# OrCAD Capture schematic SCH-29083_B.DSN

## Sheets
1 02 NOTES: title: TWR-CM3120-EVM; rev: B; company: NXP SEMICONDUCTORS; note: SCH-29083 PDF: SPF-29083; note: 6501 William Cannon Drive West; note: Austin, TX 78735-8598
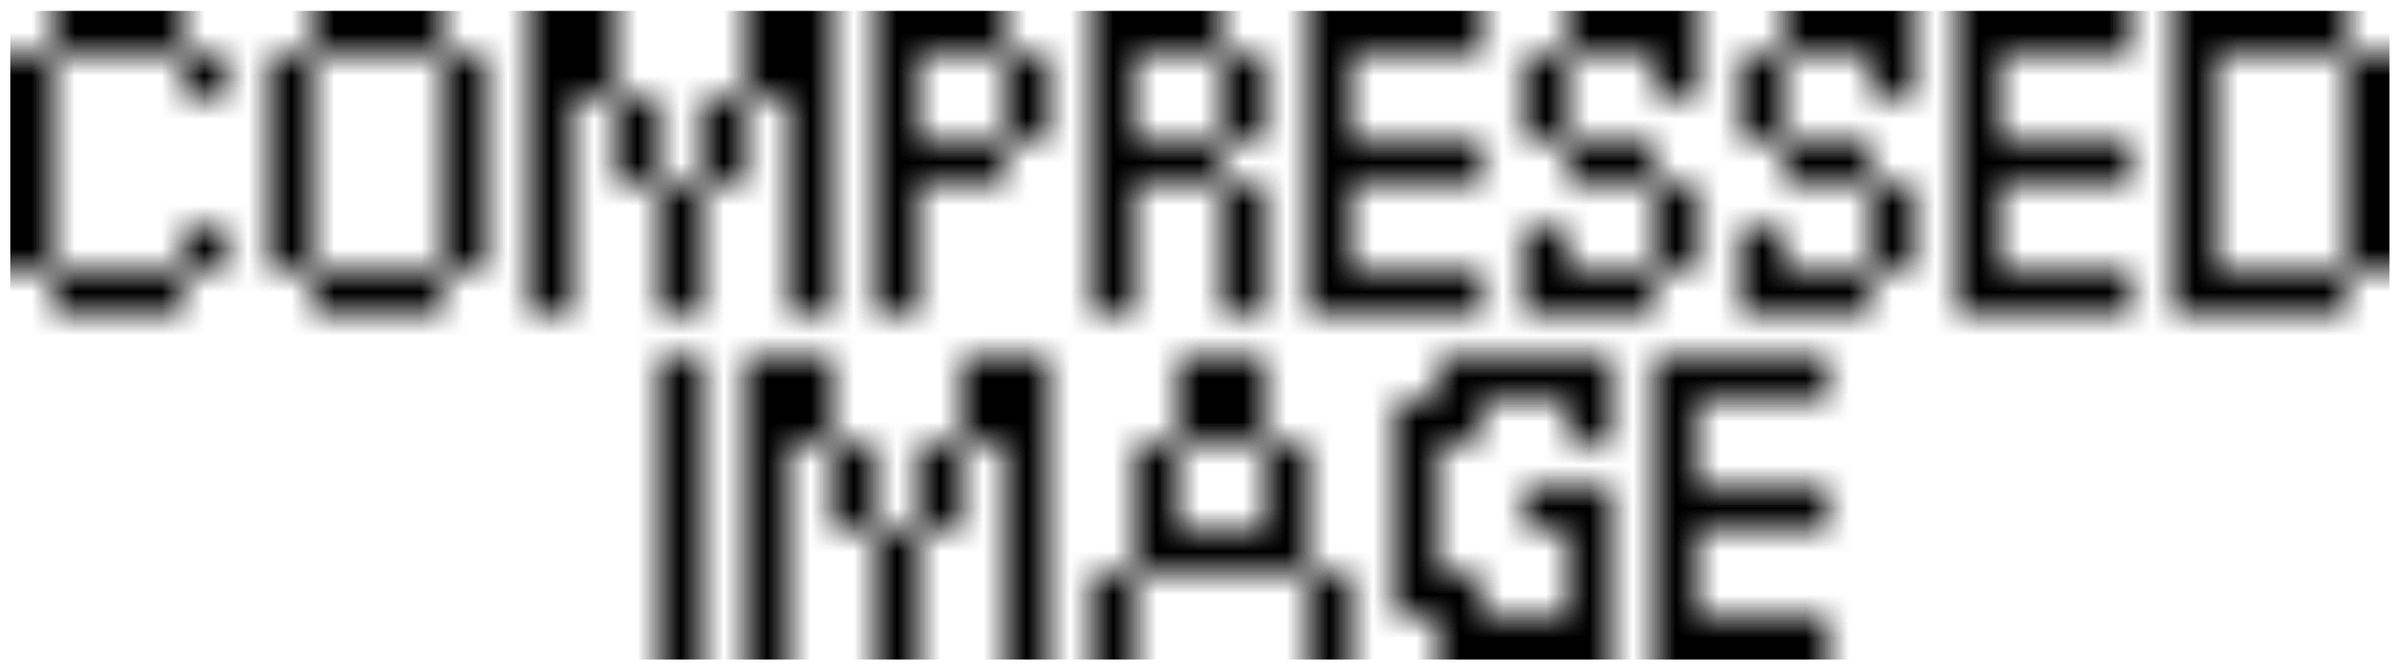
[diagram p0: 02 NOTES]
2 01 TITLE, TOC & REV
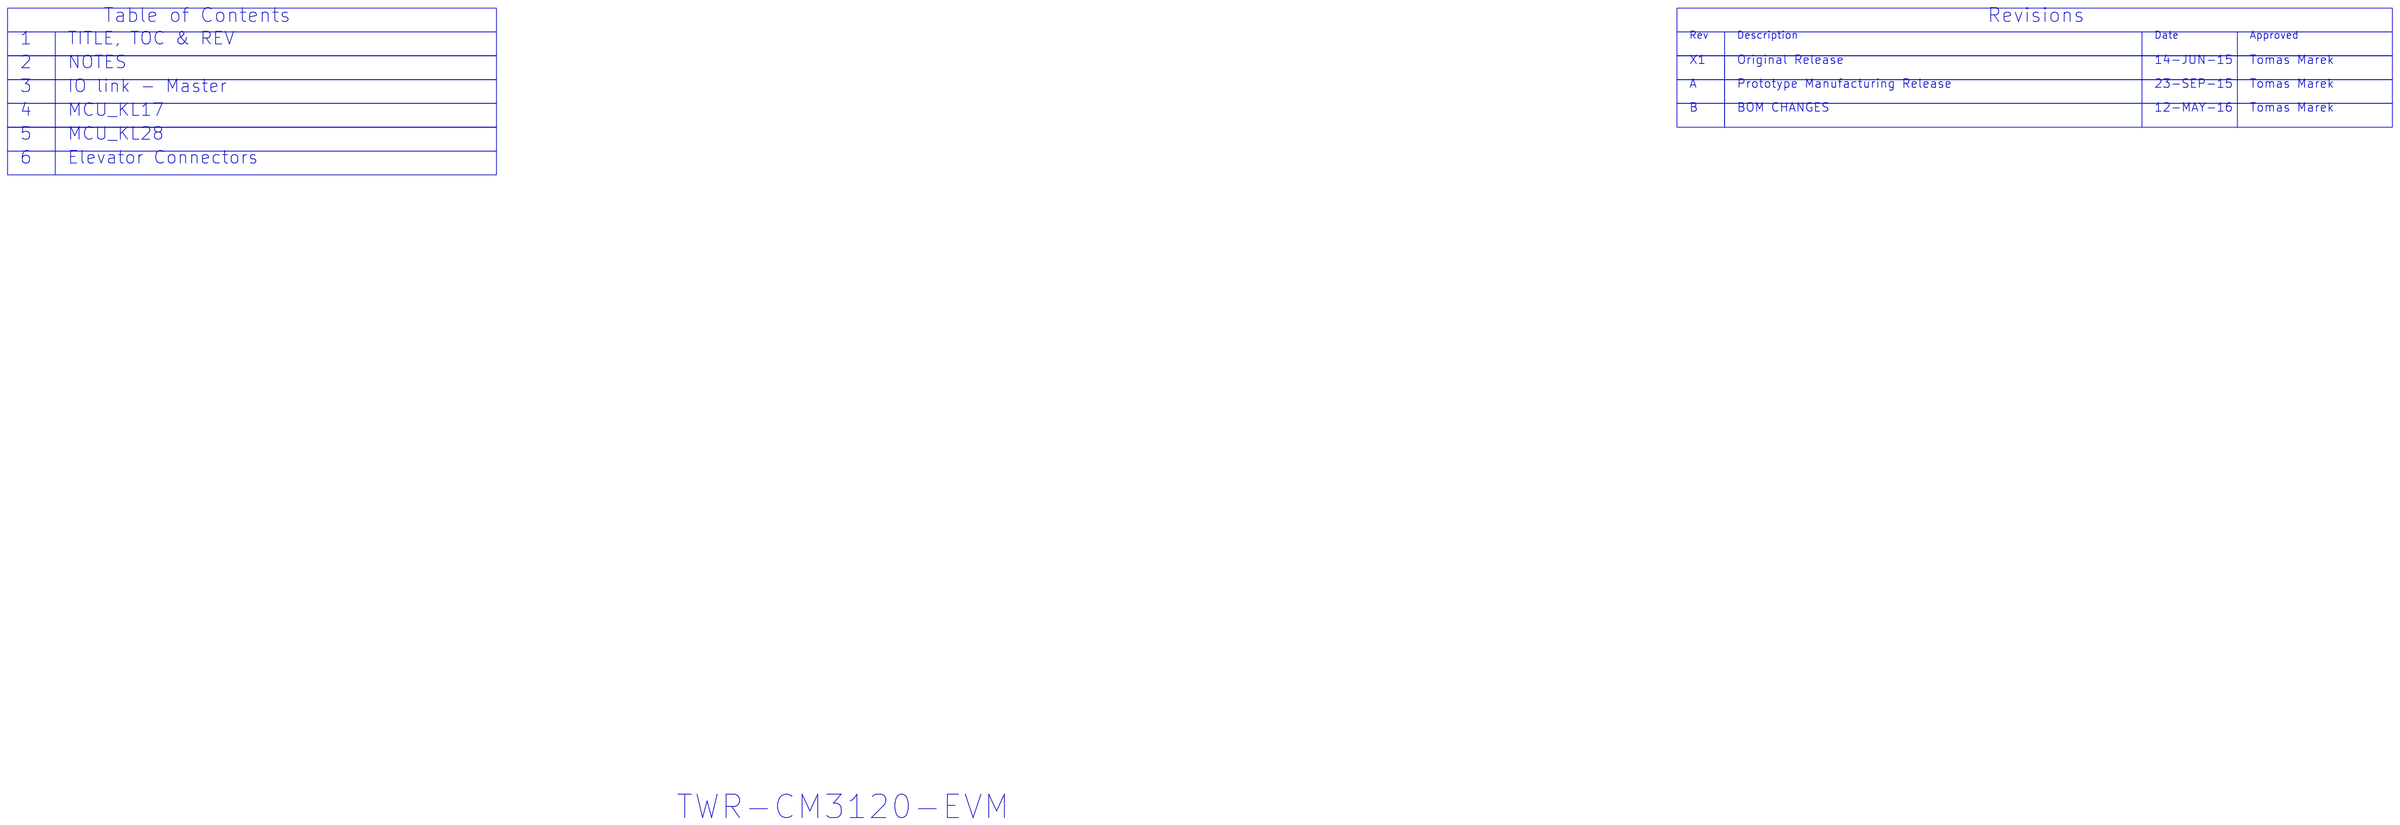
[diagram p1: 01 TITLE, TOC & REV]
3 03 IO link - Master: size C
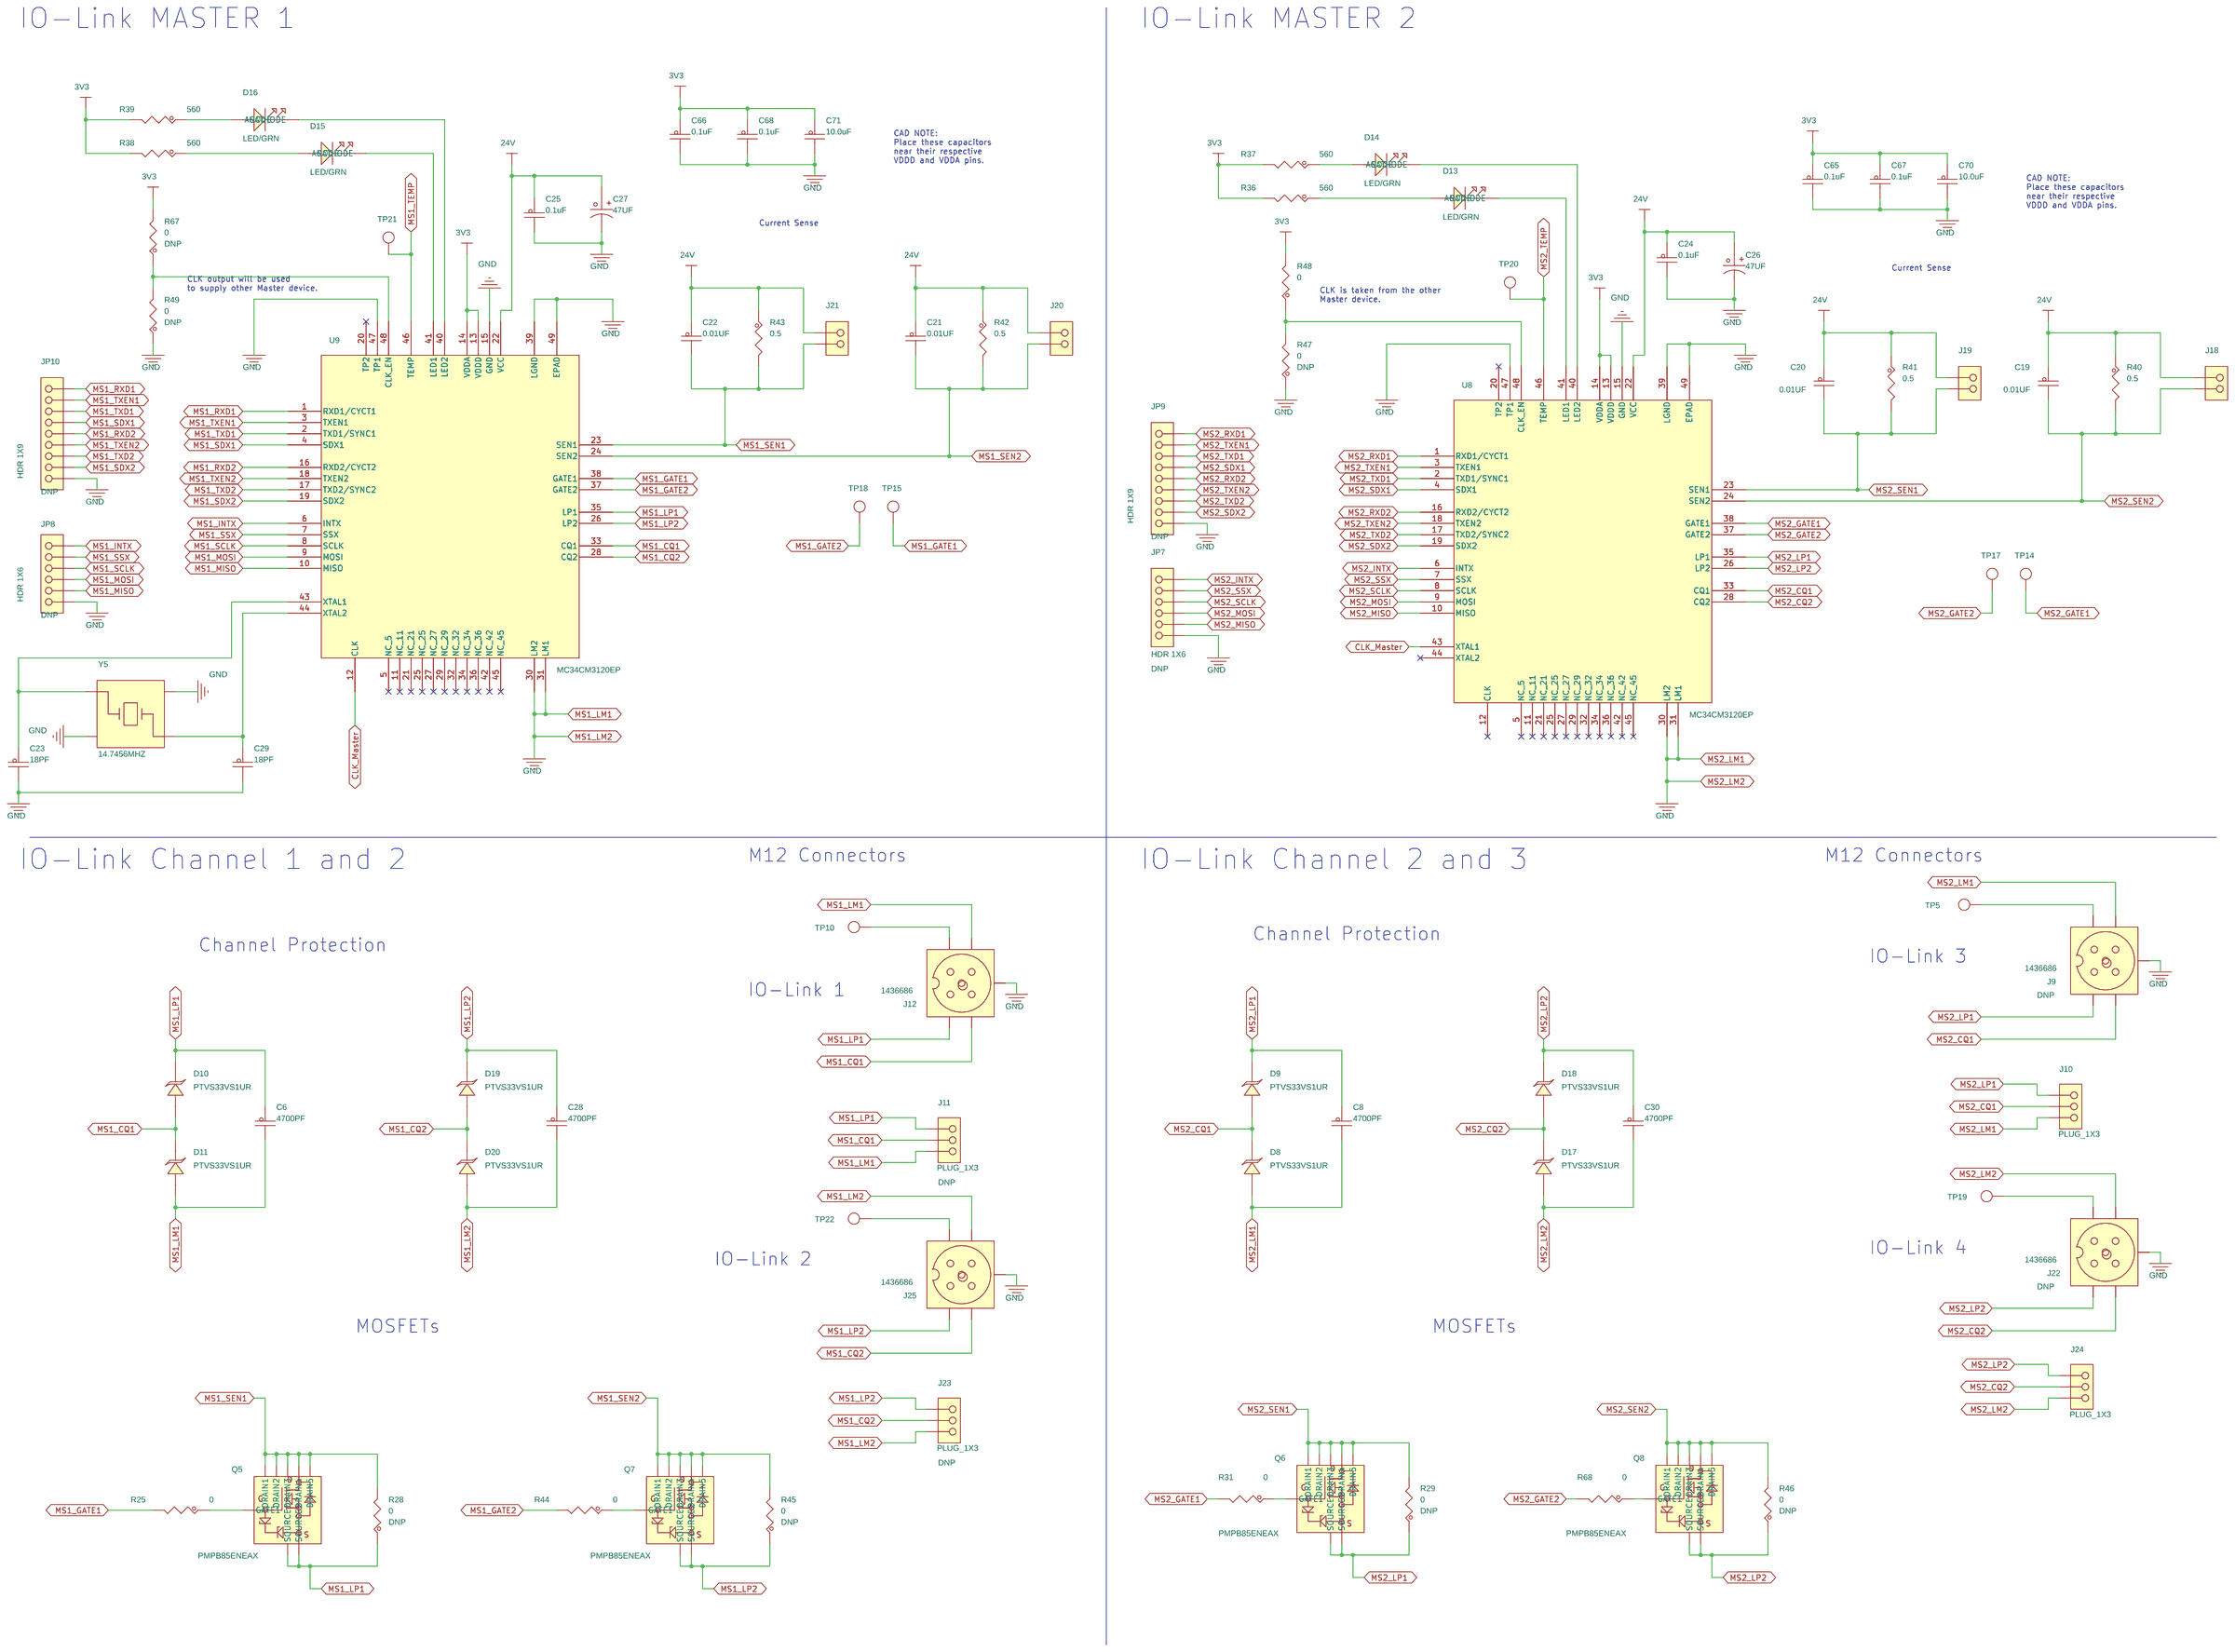
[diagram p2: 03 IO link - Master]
4 04 MCU_KL17: size C
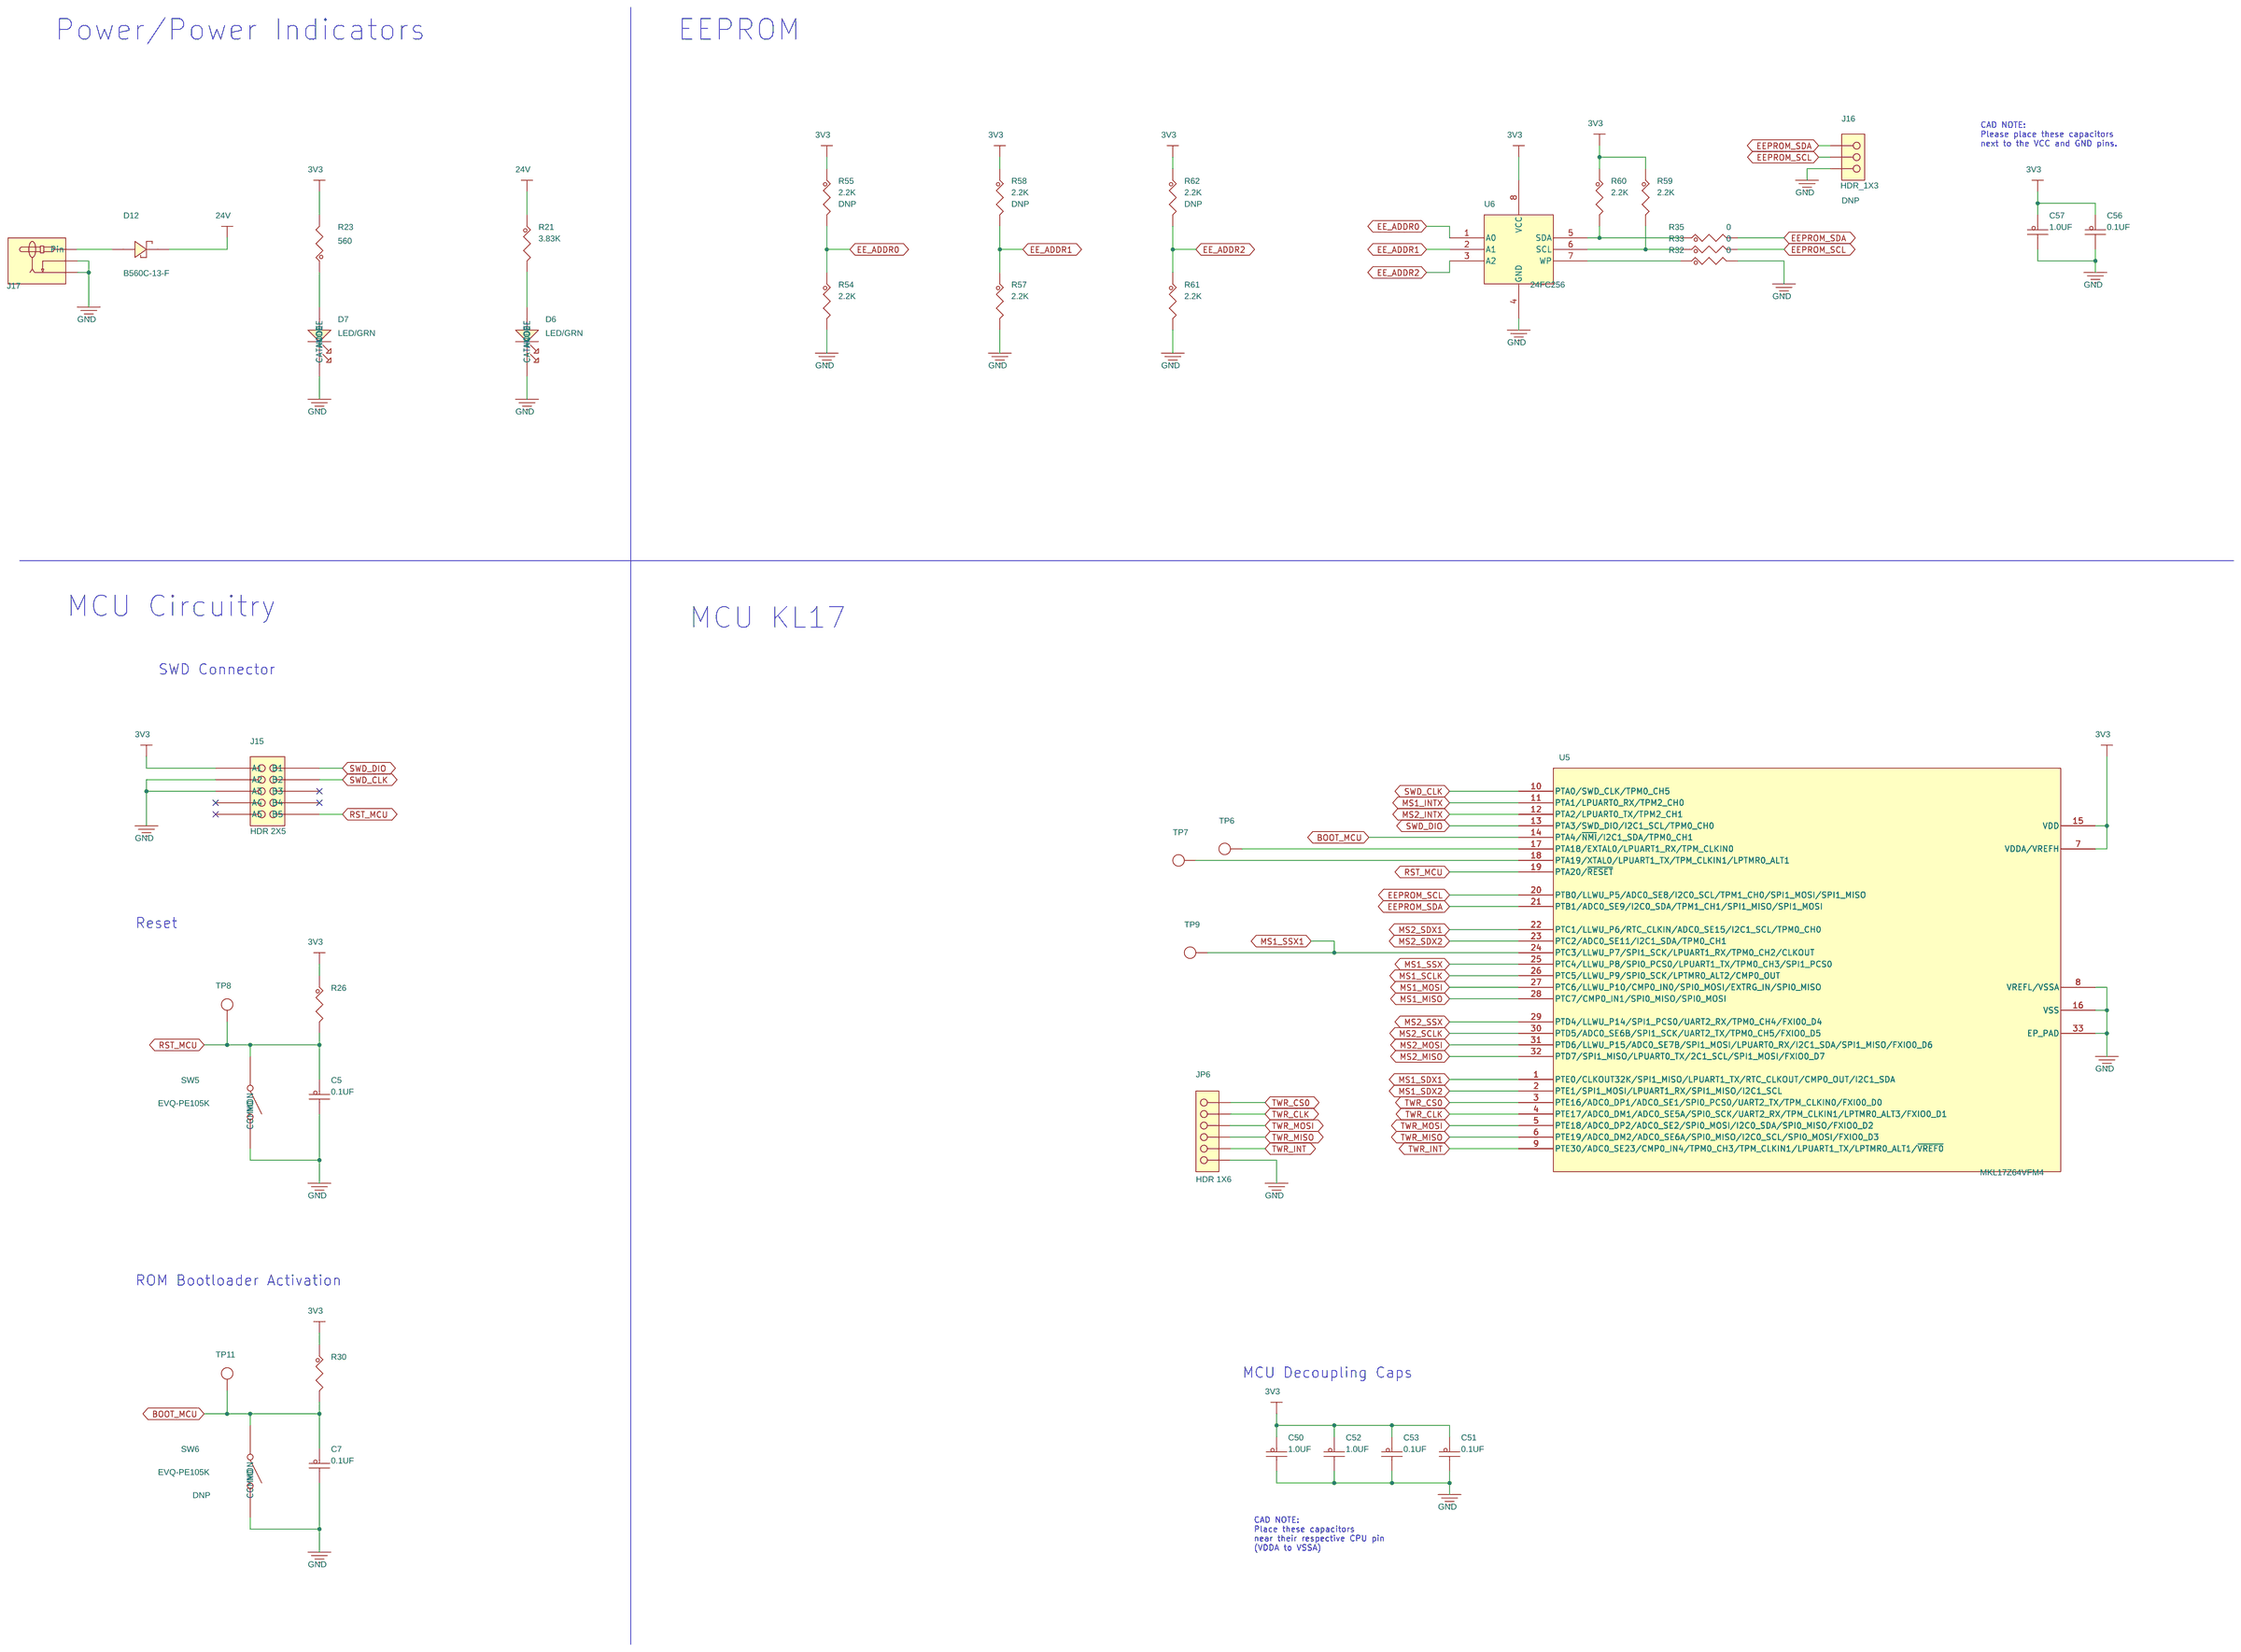
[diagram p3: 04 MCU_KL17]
5 06 Elevator Connectors: size C
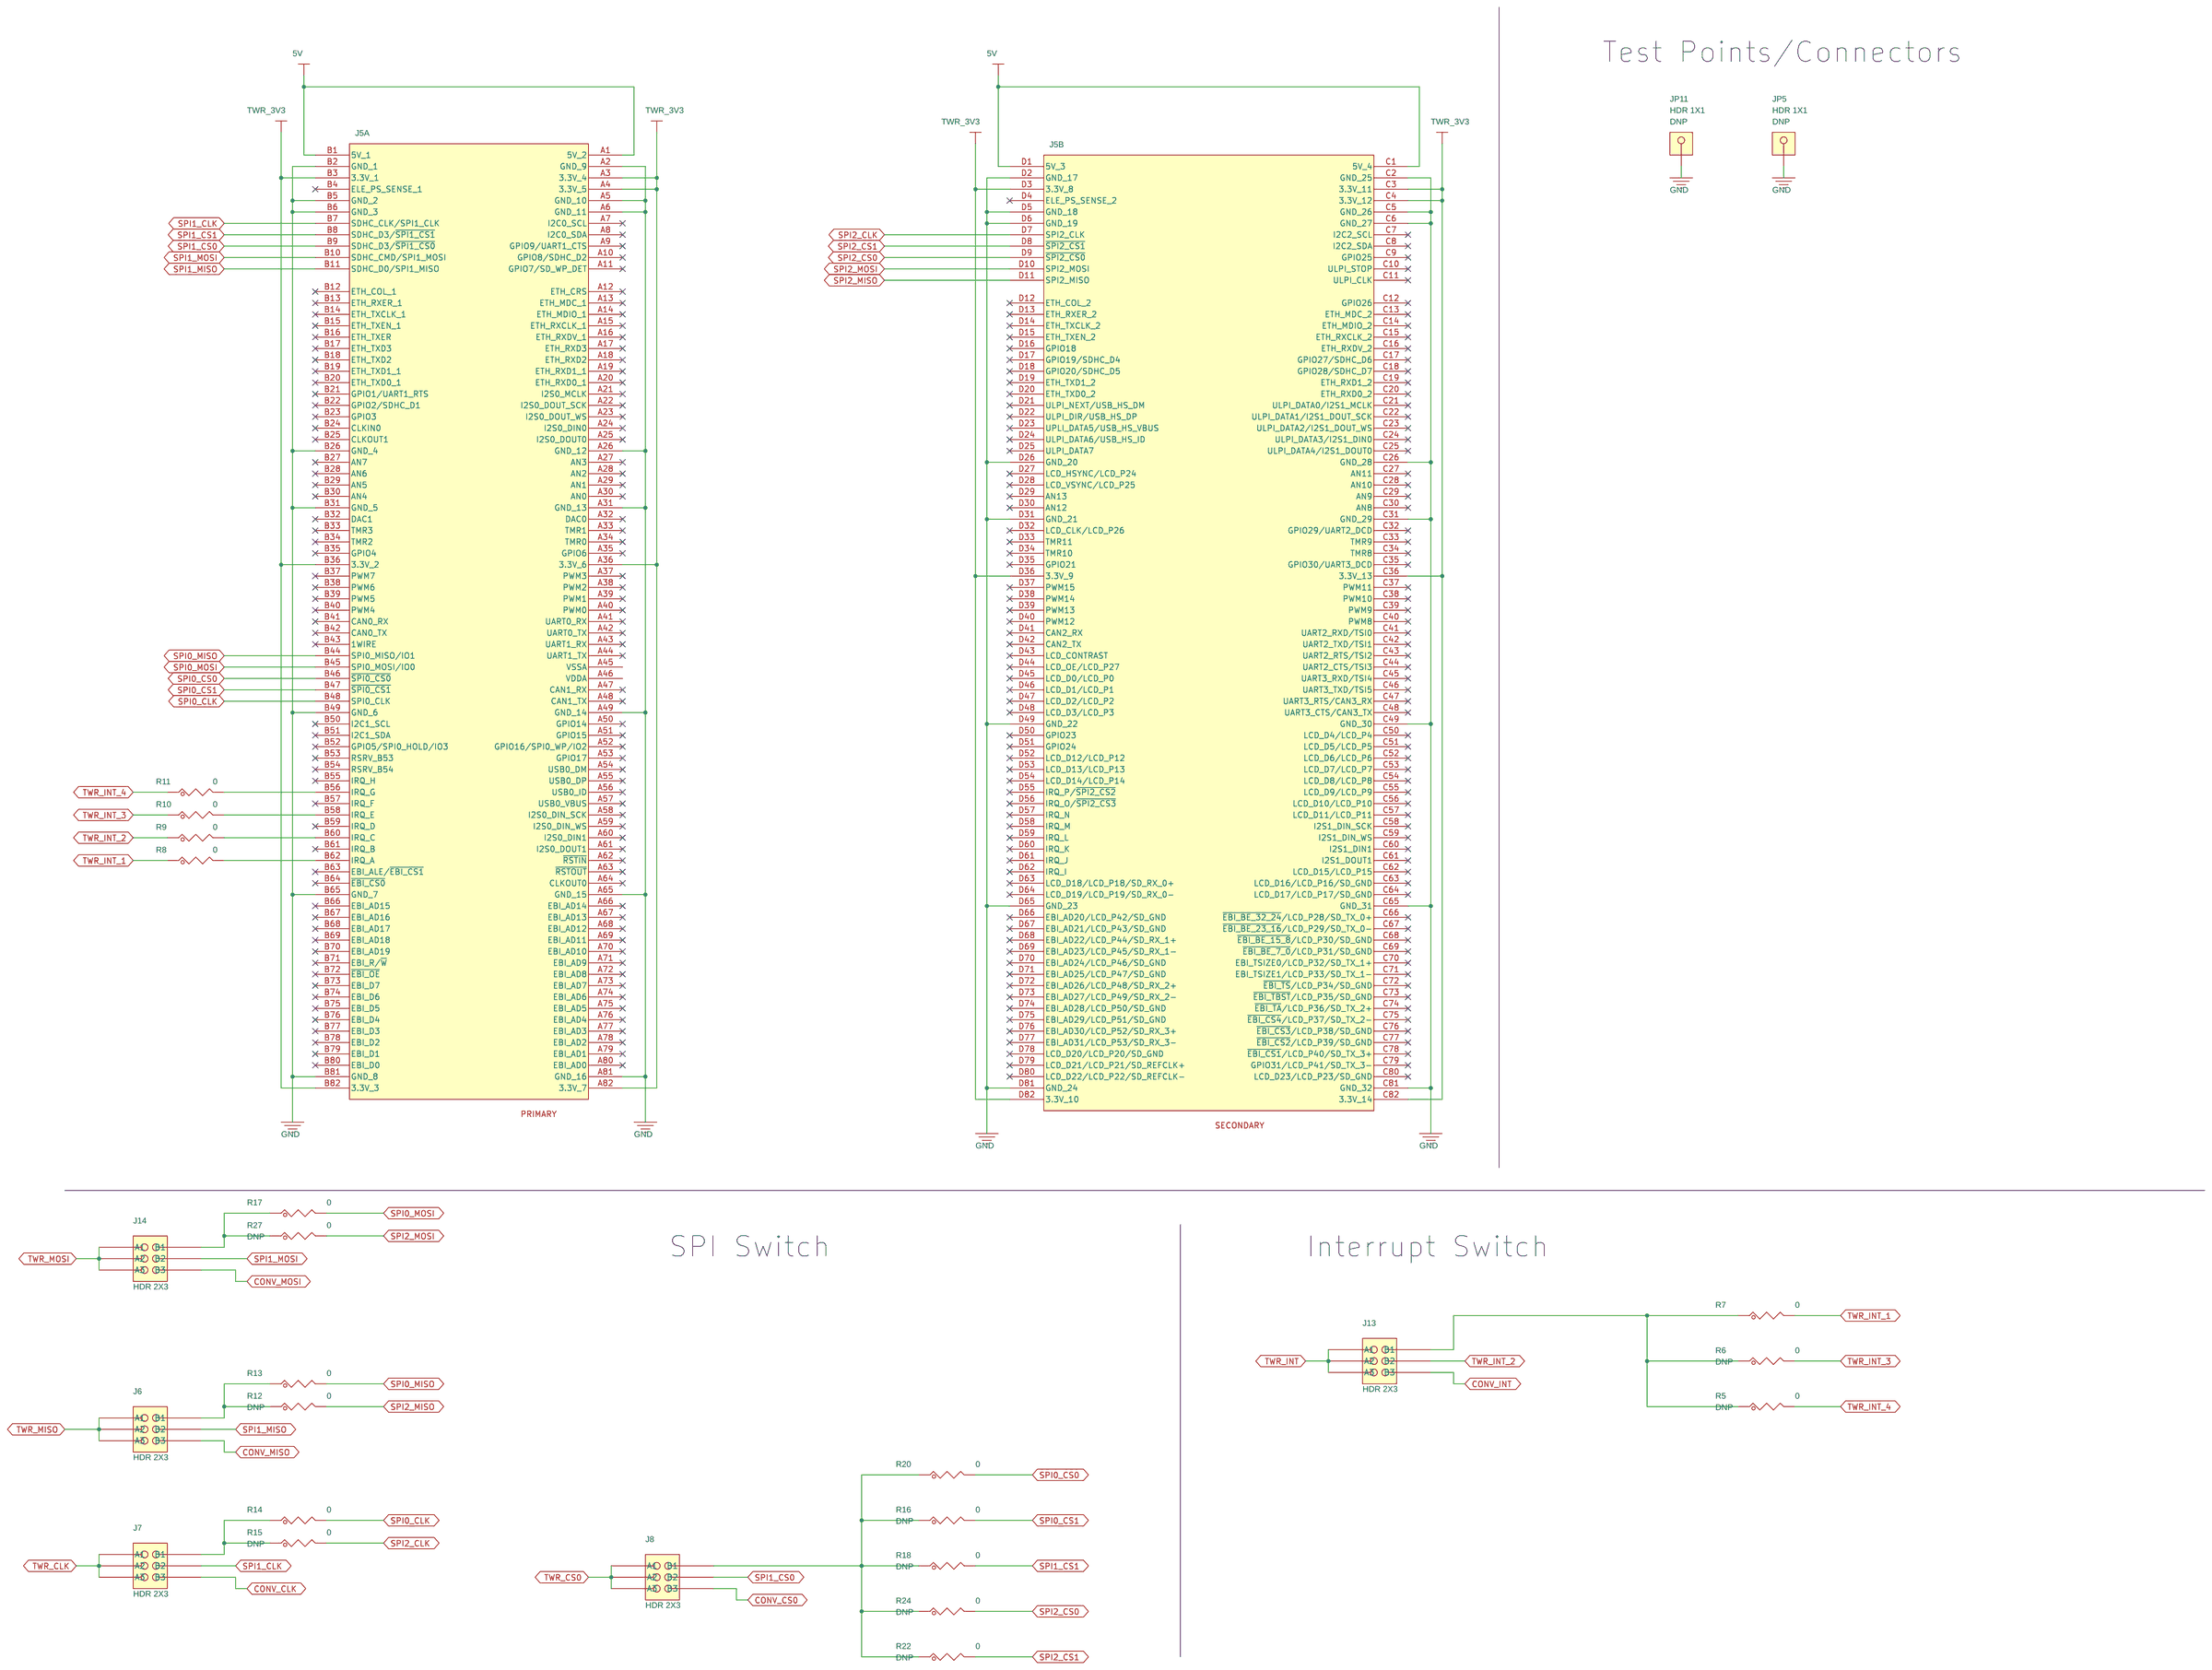
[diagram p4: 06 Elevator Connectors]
6 07 SPI/USB Converter - KL25: size C
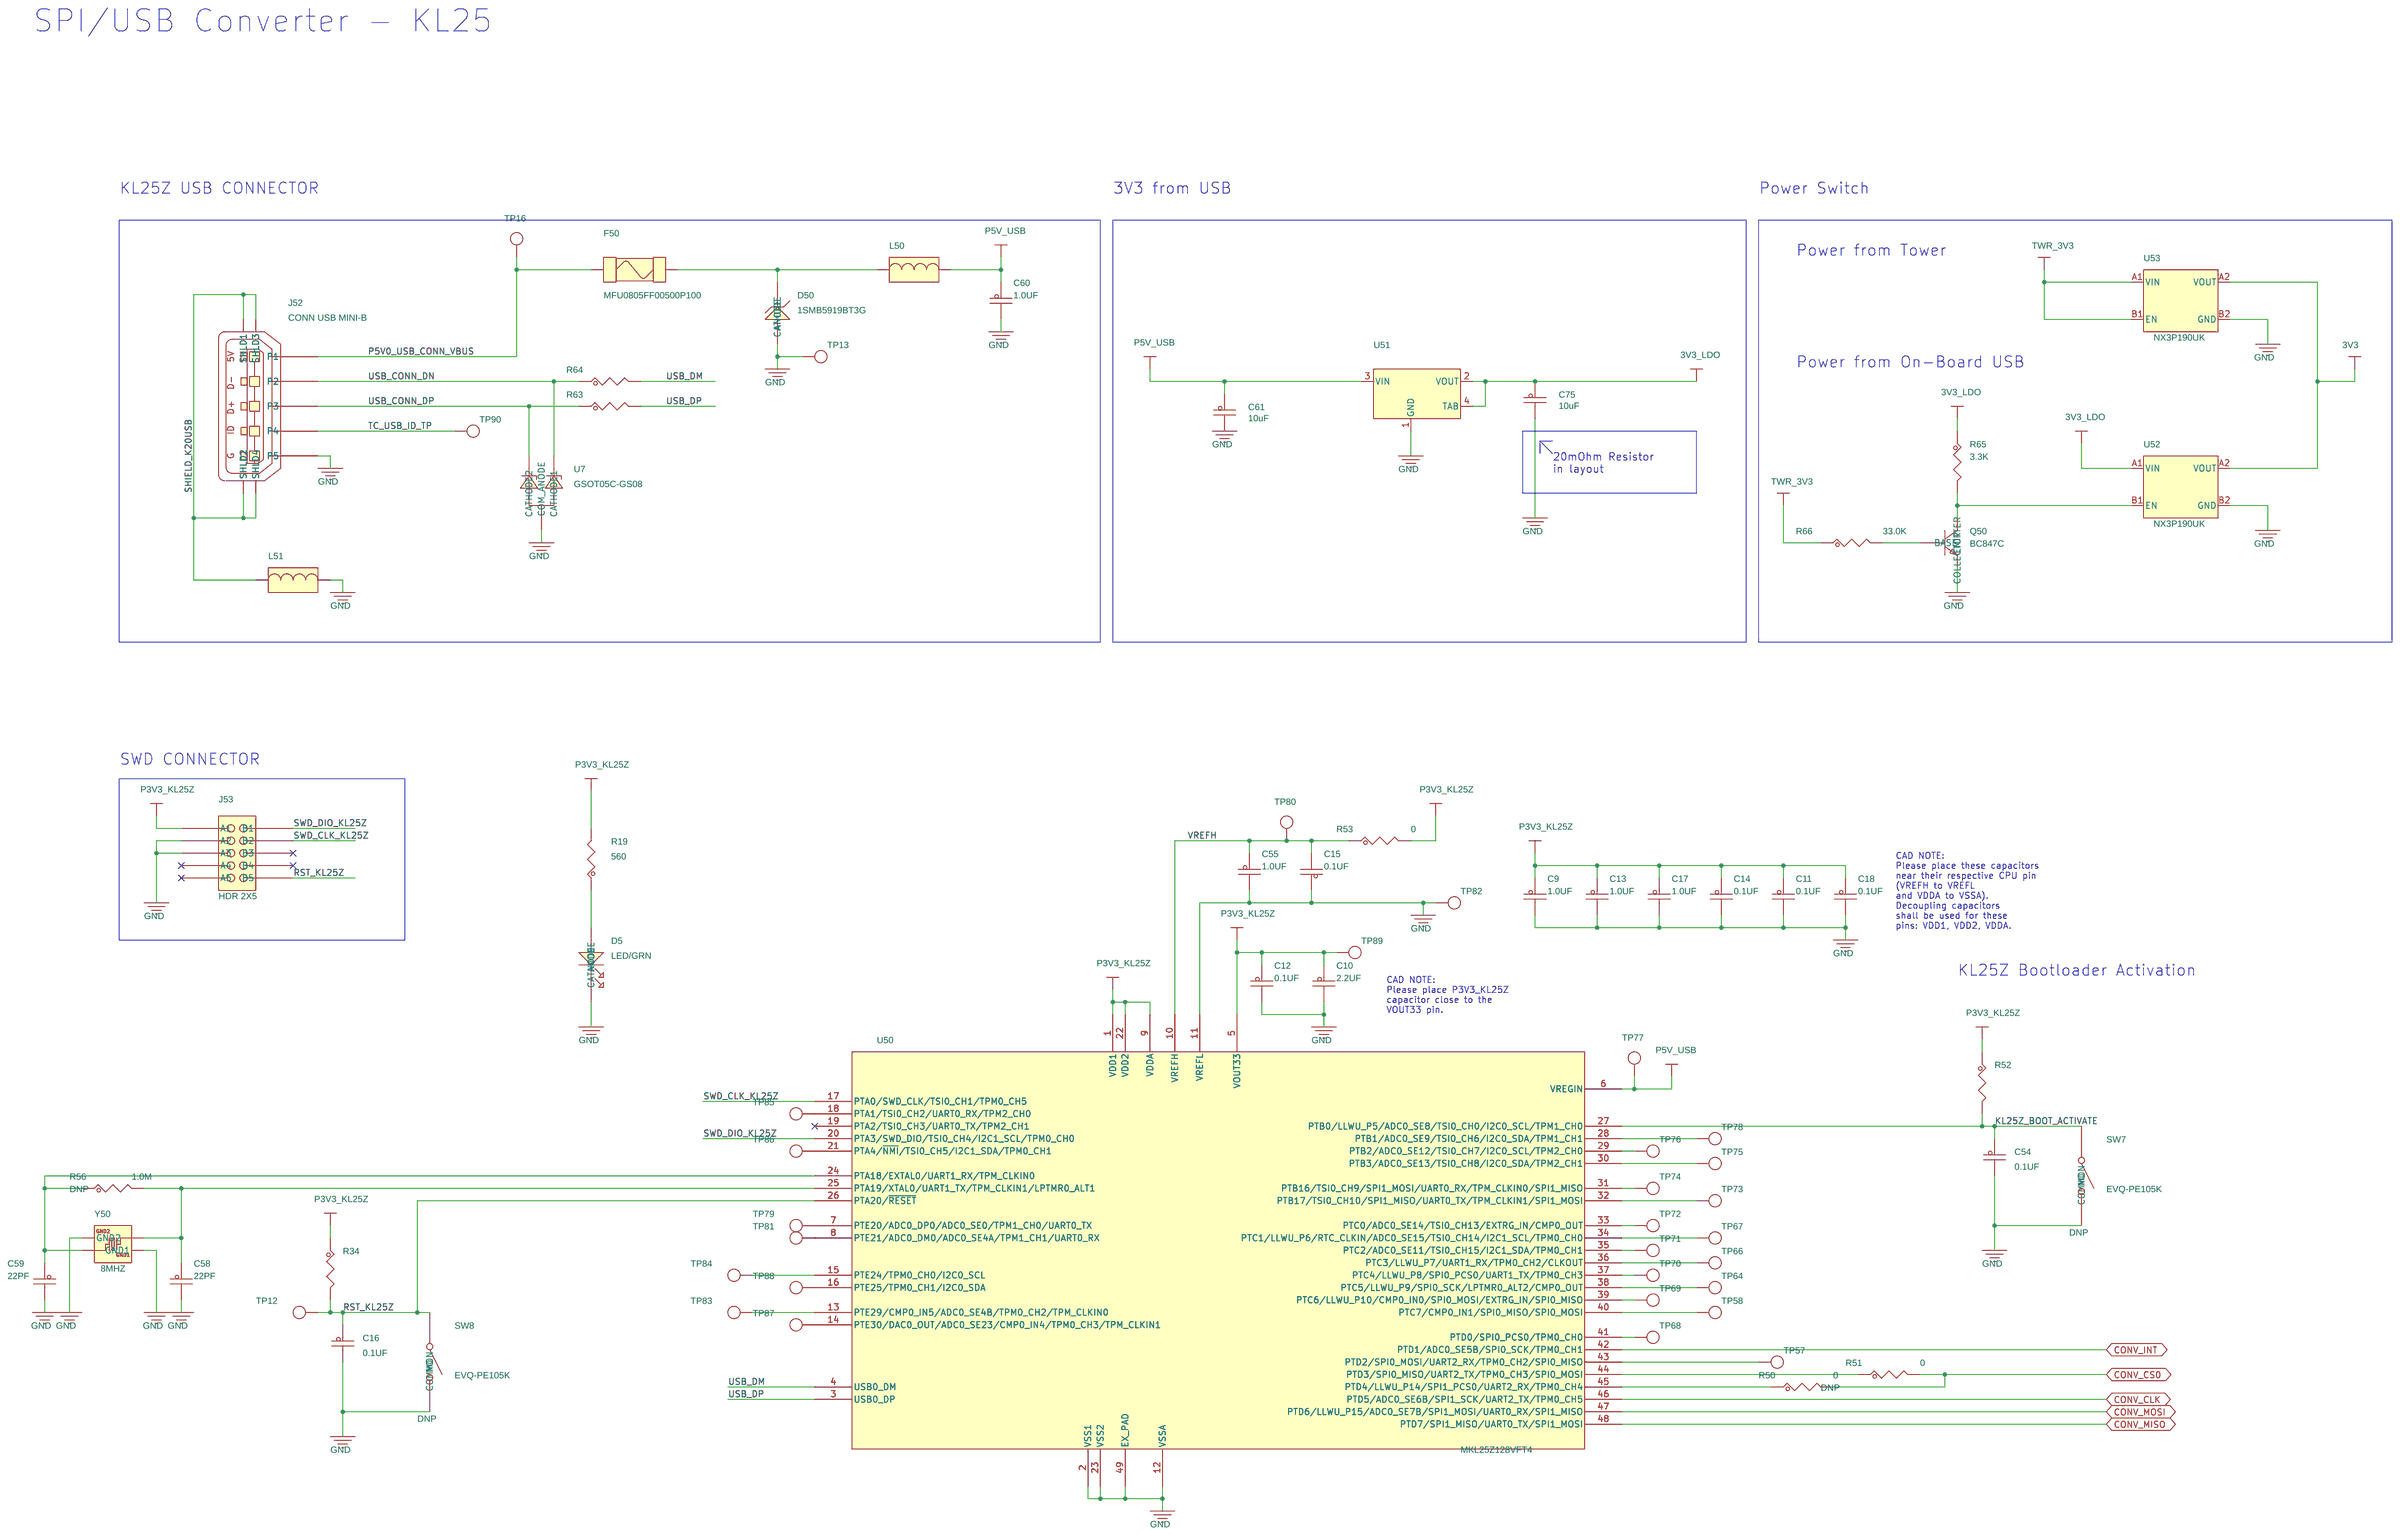
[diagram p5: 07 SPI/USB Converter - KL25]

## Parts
sheet 03 IO link - Master
C6  4700PF  [CC0603_OV]
C8  4700PF  [CC0603_OV]
C19  0.01UF  [CC0402_25]
C20  0.01UF  [CC0402_25]
C21  0.01UF  [CC0402_25]
C22  0.01UF  [CC0402_25]
C23  18PF  [CC0402_25]
C24  0.1uF  [CC0402_25]
C25  0.1uF  [CC0402_25]
C26  47UF  [case_d_al]
C27  47UF  [case_d_al]
C28  4700PF  [CC0603_OV]
C29  18PF  [CC0402_25]
C30  4700PF  [CC0603_OV]
C65  0.1uF  [CC0402_25]
C66  0.1uF  [CC0402_25]
C67  0.1uF  [CC0402_25]
C68  0.1uF  [CC0402_25]
C70  10.0uF  [CC0805_OV]
C71  10.0uF  [CC0805_OV]
D8  PTVS33VS1UR  [sod123w]
D9  PTVS33VS1UR  [sod123w]
D10  PTVS33VS1UR  [sod123w]
D11  PTVS33VS1UR  [sod123w]
D13  LED/GRN  [led2_2p1x1p5_nsp]
D14  LED/GRN  [led2_2p1x1p5_nsp]
D15  LED/GRN  [led2_2p1x1p5_nsp]
D16  LED/GRN  [led2_2p1x1p5_nsp]
D17  PTVS33VS1UR  [sod123w]
D18  PTVS33VS1UR  [sod123w]
D19  PTVS33VS1UR  [sod123w]
D20  PTVS33VS1UR  [sod123w]
J9  1436686  [con5_th_1436686]
J10  PLUG_1X3  [con1x3_3p81_9p2x12p82]
J11  PLUG_1X3  [con1x3_3p81_9p2x12p82]
J12  1436686  [con5_th_1436686]
J18  HDR 1X2  [HDR102]
J19  HDR 1X2  [HDR102]
J20  HDR 1X2  [HDR102]
J21  HDR 1X2  [HDR102]
J22  1436686  [con5_th_1436686]
J23  PLUG_1X3  [con1x3_3p81_9p2x12p82]
J24  PLUG_1X3  [con1x3_3p81_9p2x12p82]
J25  1436686  [con5_th_1436686]
JP7  HDR 1X6  [hdr106_th_tsw]
JP8  HDR 1X6  [hdr106_th_tsw]
JP9  HDR 1X9  [hdr109]
JP10  HDR 1X9  [hdr109]
Q5  PMPB85ENEAX  [sot1220]
Q6  PMPB85ENEAX  [sot1220]
Q7  PMPB85ENEAX  [sot1220]
Q8  PMPB85ENEAX  [sot1220]
R25  0  [RC0603_OV]
R28  0  [RC0603_OV]
R29  0  [RC0603_OV]
R31  0  [RC0603_OV]
R36  560  [RC0603_OV]
R37  560  [RC0603_OV]
R38  560  [RC0603_OV]
R39  560  [RC0603_OV]
R40  0.5  [RC1206_OV]
R41  0.5  [RC1206_OV]
R42  0.5  [RC1206_OV]
R43  0.5  [RC1206_OV]
R44  0  [RC0603_OV]
R45  0  [RC0603_OV]
R46  0  [RC0603_OV]
R47  0  [RC0603_OV]
R48  0  [RC0603_OV]
R49  0  [RC0603_OV]
R67  0  [RC0603_OV]
R68  0  [RC0603_OV]
TP5  TPAD_030  [TPAD_030]
TP10  TPAD_030  [TPAD_030]
TP14  TPAD_030  [TPAD_030]
TP15  TPAD_030  [TPAD_030]
TP17  TPAD_030  [TPAD_030]
TP18  TPAD_030  [TPAD_030]
TP19  TPAD_030  [TPAD_030]
TP20  TPAD_030  [TPAD_030]
TP21  TPAD_030  [TPAD_030]
TP22  TPAD_030  [TPAD_030]
U8  MC34CM3120EP  [qfn48_0p5_7x7_ep3p9_nsp]
U9  MC34CM3120EP  [qfn48_0p5_7x7_ep3p9_nsp]
Y5  14.7456MHZ  [xtal_4_7x5]
sheet 04 MCU_KL17
C5  0.1UF  [CC0402_25]
C7  0.1UF  [CC0402_25]
C50  1.0UF  [CC0402_25]
C51  0.1UF  [CC0402_25]
C52  1.0UF  [CC0402_25]
C53  0.1UF  [CC0402_25]
C56  0.1UF  [CC0402_25]
C57  1.0UF  [CC0402_25]
D6  LED/GRN  [led2_2p1x1p5_nsp]
D7  LED/GRN  [led2_2p1x1p5_nsp]
D12  B560C-13-F  [SMC_CASE403]
J15  HDR 2X5  [hdr_5X2_ftsh_th]
J16  HDR_1X3  [HDR103]
J17  CON_1_PWR  [PJ-102AH]
JP6  HDR 1X6  [hdr106_th_tsw]
R21  3.83K  [RC0603_OV]
R23  560  [RC0603_OV]
R26  10K  [RC0603_OV]
R30  10K  [RC0603_OV]
R32  0  [RC0603_OV]
R33  0  [RC0603_OV]
R35  0  [RC0603_OV]
R54  2.2K  [RC0603_OV]
R55  2.2K  [RC0603_OV]
R57  2.2K  [RC0603_OV]
R58  2.2K  [RC0603_OV]
R59  2.2K  [RC0402_25]
R60  2.2K  [RC0402_25]
R61  2.2K  [RC0603_OV]
R62  2.2K  [RC0603_OV]
SW5  EVQ-PE105K  [sw2_spst_3p5x6p0_5p0]
SW6  EVQ-PE105K  [sw2_spst_3p5x6p0_5p0]
TP6  TPAD_030  [TPAD_030]
TP7  TPAD_030  [TPAD_030]
TP8  TPAD_030  [TPAD_030]
TP9  TPAD_030  [TPAD_030]
TP11  TPAD_030  [TPAD_030]
U5  MKL17Z64VFM4  [QFN32_S142EP]
U6  24FC256  [TSSOP8]
sheet 06 Elevator Connectors
J5  PCI EXPRESS TOWER SYSTEM  [cn2x82_finger_ass]  (sections A,B)
J6  HDR 2X3  [HDR203]
J7  HDR 2X3  [HDR203]
J8  HDR 2X3  [HDR203]
J13  HDR 2X3  [HDR203]
J14  HDR 2X3  [HDR203]
JP5  HDR 1X1  [HDR101]
JP11  HDR 1X1  [HDR101]
R5  0  [RC0603_OV]
R6  0  [RC0603_OV]
R7  0  [RC0603_OV]
R8  0  [RC0603_OV]
R9  0  [RC0603_OV]
R10  0  [RC0603_OV]
R11  0  [RC0603_OV]
R12  0  [RC0603_OV]
R13  0  [RC0603_OV]
R14  0  [RC0603_OV]
R15  0  [RC0603_OV]
R16  0  [RC0603_OV]
R17  0  [RC0603_OV]
R18  0  [RC0603_OV]
R20  0  [RC0603_OV]
R22  0  [RC0603_OV]
R24  0  [RC0603_OV]
R27  0  [RC0603_OV]
sheet 07 SPI/USB Converter - KL25
C9  1.0UF  [CC0402_25]
C10  2.2UF  [CC0805_OV]
C11  0.1UF  [CC0402_25]
C12  0.1UF  [CC0402_25]
C13  1.0UF  [CC0402_25]
C14  0.1UF  [CC0402_25]
C15  0.1UF  [CC0402_25]
C16  0.1UF  [CC0402_25]
C17  1.0UF  [CC0402_25]
C18  0.1UF  [CC0402_25]
C54  0.1UF  [CC0402_25]
C55  1.0UF  [CC0402_25]
C58  22PF  [CC0402_25]
C59  22PF  [CC0402_25]
C60  1.0UF  [CC0402_25]
C61  10uF  [CC0603_OV]
C75  10uF  [CC0603_OV]
D5  LED/GRN  [led2_2p1x1p5_nsp]
D50  1SMB5919BT3G  [CASE403A_03]
F50  MFU0805FF00500P100  [fuse_2x1p4]
J52  CONN USB MINI-B  [con5_usb_ra_smt]
J53  HDR 2X5  [hdr_5X2_ftsh_th]
L50  330 OHM  [IND_0805]
L51  330 OHM  [IND_0805]
Q50  BC847C  [sot23-40x40]
R19  560  [RC0603_OV]
R34  10K  [RC0603_OV]
R50  0  [RC0402_25]
R51  0  [RC0402_25]
R52  10K  [RC0603_OV]
R53  0  [RC0402_25]
R56  1.0M  [RC0603_OV]
R63  33  [RC0402_25]
R64  33  [RC0402_25]
R65  3.3K  [RC0603_OV]
R66  33.0K  [RC0603_OV]
SW7  EVQ-PE105K  [sw2_spst_3p5x6p0_5p0]
SW8  EVQ-PE105K  [sw2_spst_3p5x6p0_5p0]
TP12  TPAD_030  [TPAD_030]
TP13  TESTLOOP_BLACK  [tp_th_063]
TP16  TESTLOOP_RED  [tp_th_063]
TP57  TPAD_030  [TPAD_030]
TP58  TPAD_030  [TPAD_030]
TP64  TPAD_030  [TPAD_030]
TP66  TPAD_030  [TPAD_030]
TP67  TPAD_030  [TPAD_030]
TP68  TPAD_030  [TPAD_030]
TP69  TPAD_030  [TPAD_030]
TP70  TPAD_030  [TPAD_030]
TP71  TPAD_030  [TPAD_030]
TP72  TPAD_030  [TPAD_030]
TP73  TPAD_030  [TPAD_030]
TP74  TPAD_030  [TPAD_030]
TP75  TPAD_030  [TPAD_030]
TP76  TPAD_030  [TPAD_030]
TP77  TPAD_030  [TPAD_030]
TP78  TPAD_030  [TPAD_030]
TP79  TPAD_030  [TPAD_030]
TP80  TPAD_030  [TPAD_030]
TP81  TPAD_030  [TPAD_030]
TP82  TPAD_030  [TPAD_030]
TP83  TPAD_030  [TPAD_030]
TP84  TPAD_030  [TPAD_030]
TP85  TPAD_030  [TPAD_030]
TP86  TPAD_030  [TPAD_030]
TP87  TPAD_030  [TPAD_030]
TP88  TPAD_030  [TPAD_030]
TP89  TPAD_030  [TPAD_030]
TP90  TPAD_030  [TPAD_030]
U7  GSOT05C-GS08  [sot23_a]
U50  MKL25Z128VFT4  [QFN_48_0P5_7X7]
U51  NCP1117ST33T3G  [sot223]
U52  NX3P190UK  [wlcsp4_0p4_0p8x0p8_smdp]
U53  NX3P190UK  [wlcsp4_0p4_0p8x0p8_smdp]
Y50  8MHZ  [xtlosc4_5x3MM_sm]

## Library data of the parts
C6 C8 C28 C30 = CAP_NP: CAP CER 4700PF 50V 10% X7R 0603; AGILE_PN: 150-30078; CAD_APPROVED: Yes; FPLIST: CC0603_OV,CC0603,0603_CC; HEIGHT: 0.90MM; MFG_NAME01: YAGEO AMERICA; MFG_PN01: CC0603KRX7R9BB472; ROHS: Yes; Tolerance: 10%; VOLTAGE: 50V
C19-C22 = CAP_NP: CAP CER 0.01UF 50V 10% X7R 0402; AGILE_PN: 150-30114; CAD_APPROVED: Yes; FPLIST: CC0402_25,CC0402_HD,0402_CC; HEIGHT: 0.74 MM; MFG_NAME01: WALSIN TECHNOLOGY CORP.; MFG_PN01: 0402B103K500CT; ROHS: Yes; Tolerance: 10%; VOLTAGE: 50V
C23 C29 = CAP_NP: CAP CER 18PF 50V 1% C0G 0402; AGILE_PN: 150-76630; CAD_APPROVED: Yes; FPLIST: CC0402_25,CC0402_HD,0402_CC; HEIGHT: 0.59MM; MFG_NAME01: YAGEO; MFG_PN01: CC0402FRNPO9BN180; ROHS: Yes; Tolerance: 1%; VOLTAGE: 50V
C24 C25 C65-C68 = CAP_NP: CAP CER 0.1uF 50V 10% X7R AEC-Q200 0402; AGILE_PN: 150-79461; CAD_APPROVED: Yes; FPLIST: CC0402_25,CC0402_HD,0402_CC; HEIGHT: 0.55MM; MFG_NAME01: TDK; MFG_PN01: CGA2B3X7R1H104K050BB; ROHS: Yes; Tolerance: 10%; VOLTAGE: 50V
C26 C27 = CAP_POL: CAP ALEL 47uF 50V 20% -- SMT; AGILE_PN: 150-79243; CAD_APPROVED: Yes; HEIGHT: 8MM; MFG_NAME01: PANASONIC; MFG_PN01: EEEFK1H470XP; ROHS: Yes; Tolerance: 20%; VOLTAGE: 50V
C70 C71 = CAP_NP: CAP CER 10UF 16V 10% X7R 0805; AGILE_PN: 150-30139; CAD_APPROVED: Yes; FPLIST: CC0805_OV,CC0805,0805_CC; HEIGHT: 1.27mm; MFG_NAME01: CAPAX TECHNOLOGIES INC.; MFG_PN01: 0805X106K160SNT; ROHS: Yes; Tolerance: 10%; VOLTAGE: 16V
D8-D11 D17-D20 = DIODE_TVS: DIODE TVS 400W AEC-Q101 SOD123W; AGILE_PN: 480-79026; CAD_APPROVED: Yes; HEIGHT: 1.1MM; MFG_NAME01: NXP SEMICONDUCTORS; MFG_PN01: PTVS33VS1UR,115; ROHS: Yes
D5-D7 D13-D16 = LED: LED GRN SGL 20mA SMT; AGILE_PN: 370-76595; CAD_APPROVED: Yes; FPLIST: led2_2p1x1p5,led2_2p1x1p5_nsp; HEIGHT: 1.4 MM; MFG_NAME01: OSRAM; MFG_PN01: LP M67K-E2G1-25; ROHS: Yes
J9 J22 = CON5_DIN: CON 5 IO-LINK PLUG RA TH -- 626H AU --; AGILE_PN: TMP-WF-27345; ASSY_OPT: DNP; CAD_APPROVED: Yes; HEIGHT: 15.9MM; MFG_NAME01: Phoenix Contact; PRE_APN: 210-81111; ROHS: Yes
J10 J24 = CONN_HDR_3X1: CON 1X3 PLUG SHRD RA TH 3.81MM SP 285H SN 134L; AGILE_PN: 210-80543; CAD_APPROVED: Yes; HEIGHT: 7.25MM; MFG_NAME01: PHOENIX CONTACT; MFG_PN01: 1803280; ROHS: Yes
J11 J23 = CONN_HDR_3X1: CON 1X3 PLUG SHRD RA TH 3.81MM SP 285H SN 134L; AGILE_PN: 210-80543; ASSY_OPT: DNP; CAD_APPROVED: Yes; HEIGHT: 7.25MM; MFG_NAME01: PHOENIX CONTACT; MFG_PN01: 1803280; ROHS: Yes
J12 J25 = CON5_DIN: CON 5 IO-LINK PLUG RA TH -- 626H AU --; AGILE_PN: TMP-WF-27345; CAD_APPROVED: Yes; HEIGHT: 15.9MM; MFG_NAME01: Phoenix Contact; PRE_APN: 210-81111; ROHS: Yes
J18-J21 = CONN_HDR_2X1: HDR 1X2 TH 100MIL SP 338H SN 100L; AGILE_PN: 210-80102; CAD_APPROVED: Yes; HEIGHT: 8.58MM; MFG_NAME01: SAMTEC; MFG_PN01: TSW-102-07-T-S; ROHS: Yes
JP7 JP8 = CONN_HDR_6X1: HDR 1X6 TH 100MIL SP 330H AU 100L; AGILE_PN: 210-10091-00; ASSY_OPT: DNP; CAD_APPROVED: Yes; HEIGHT: 8.38MM; MFG_NAME01: SAMTEC; MFG_PN01: TSW-106-07-S-S; ROHS: Yes
JP9 JP10 = CONN_HDR_9X1: HDR 1X9 TH 100MIL SP 330H SN; AGILE_PN: 210-76495; ASSY_OPT: DNP; CAD_APPROVED: Yes; HEIGHT: 330MIL; MFG_NAME01: SAMTEC; MFG_PN01: TSW-109-07-T-S; ROHS: Yes
Q5-Q8 = PMPB85ENEA_SOT1220_8P: TRAN NMOS 3A 60V AEC-Q101 SOT-1220; AGILE_PN: 480-78962; CAD_APPROVED: Yes; HEIGHT: 0.65MM; MFG_NAME01: NXP SEMICONDUCTORS; ROHS: Yes
R7-R11 R13 R14 R17 R20 R25 R31-R33 R35 R44 R48 R68 = RES: RES MF ZERO OHM 1/10W -- AEC-Q200 0603; AGILE_PN: 470-75407; CAD_APPROVED: Yes; FPLIST: RC0603_OV,RC0603,R603-X2,0603_CC; HEIGHT: 0.6MM; MFG_NAME01: KOA SPEER; MFG_PN01: RK73Z1JTTD; ROHS: Yes; Tolerance: 1%
R5 R6 R12 R15 R16 R18 R22 R24 R27-R29 R45-R47 R49 R67 = RES: RES MF ZERO OHM 1/10W -- AEC-Q200 0603; AGILE_PN: 470-75407; ASSY_OPT: DNP; CAD_APPROVED: Yes; FPLIST: RC0603_OV,RC0603,R603-X2,0603_CC; HEIGHT: 0.6MM; MFG_NAME01: KOA SPEER; MFG_PN01: RK73Z1JTTD; ROHS: Yes; Tolerance: 1%
R19 R23 R36-R39 = RES: RES MF 560 1/10W 5% 0603; AGILE_PN: 470-30301; CAD_APPROVED: Yes; FPLIST: RC0603_OV,RC0603,0603_CC; HEIGHT: 0.6MM; MFG_NAME01: KOA SPEER; MFG_PN01: RK73B1JTTD561J; ROHS: Yes; TOL: 5%; Tolerance: 5%
R40-R43 = RES: RES MF 0.50 OHM 1/4W 1% 1206; AGILE_PN: 470-77300; CAD_APPROVED: Yes; FPLIST: RC1206_OV,RC1206,1206_CC; HEIGHT: 0.65MM; MFG_NAME01: VISHAY INTERTECHNOLOGY; MFG_PN01: CRCW12060R50FKEALR; ROHS: Yes; Tolerance: 1%
TP5-TP12 TP14 TP15 TP17-TP22 = TESTLOOP: TEST POINT PAD 30MIL DIA SMT, NO PART TO ORDER; AGILE_PN: 211-76642; CAD_APPROVED: Yes; HEIGHT: 0.1MM; MFG_NAME01: NOTACOMPONENT; MFG_PN01: NOTACOMPONENT; ROHS: Yes; SILK: RST_KL25Z
U8 U9 = MC34CM3120_48P: IC XCVR IO LINK 8-32V QFN48; AGILE_PN: 312-81213; CAD_APPROVED: Yes; HEIGHT: 1MM; MFG_NAME01: FREESCALE SEMICONDUCTOR; MFG_PN01: MC34CM3120EPR2; ROHS: Yes
Y5 = XTAL_13Y: XTAL 14.7456MHz 12pF SMD; AGILE_PN: 230-78063; CAD_APPROVED: Yes; HEIGHT: 1.2MM; MFG_NAME01: Euroquartz Ltd; MFG_PN01: 14.7456MHZ MQ/30/30/40/12PF; ROHS: Yes
C5 C7 C11 C12 C14-C16 C18 C51 C53 C54 C56 = CAP_NP: CAP CER 0.1UF 10V 10% X5R 0402; AGILE_PN: 150-75634; CAD_APPROVED: Yes; FPLIST: CC0402_25,CC0402_HD,0402_CC; HEIGHT: 0.64MM; MFG_NAME01: KEMET; MFG_PN01: C0402C104K8PAC; ROHS: Yes; Tolerance: 10%; VOLTAGE: 10V
C9 C13 C17 C50 C52 C55 C57 C60 = CAP_NP: CAP CER 1.0UF 10V 10% X5R 0402; AGILE_PN: 150-75772; CAD_APPROVED: Yes; FPLIST: CC0402_25,CC0402_HD,0402_CC; HEIGHT: 0.6MM; MFG_NAME01: YAGEO AMERICA; MFG_PN01: CC0402KRX5R6BB105; ROHS: Yes; VOLTAGE: 10V
D12 = DIODE_SCHTKY: DIODE SCH RECT 5A 60V AEC-Q101 SMC; AGILE_PN: 480-78849; CAD_APPROVED: Yes; HEIGHT: 2.62MM; MFG_NAME01: DIODES INC; ROHS: Yes
J15 J53 = CONN_HDR_5X2: HDR 2X5 TH 50MIL CTR 179H AU 90L; AGILE_PN: 210-80085; CAD_APPROVED: Yes; HEIGHT: 4.55MM; MFG_NAME01: SAMTEC; MFG_PN01: FTSH-105-02-F-D; ROHS: Yes
J16 = CONN_HDR_3X1: HDR 1X3 TH 100MIL SP 330H AU 98L; AGILE_PN: 210-75442; ASSY_OPT: DNP; CAD_APPROVED: Yes; HEIGHT: 8.38 MM; MFG_NAME01: SAMTEC; MFG_PN01: HTSW-103-07-S-S; ROHS: Yes
J17 = DC_POWER_JACK: CON 1 PWR PLUG DIAM 2MM RA TH -- 430H NI; AGILE_PN: 210-76612; CAD_APPROVED: Yes; HEIGHT: 11MM; MFG_NAME01: CUI STACK; PRIORITY_PN: 009-00894; ROHS: Yes; VOLTAGE: 24VDC
JP6 = CONN_HDR_6X1: HDR 1X6 TH 100MIL SP 330H AU 100L; AGILE_PN: 210-10091-00; CAD_APPROVED: Yes; HEIGHT: 8.38MM; MFG_NAME01: SAMTEC; MFG_PN01: TSW-106-07-S-S; ROHS: Yes
R21 = RES: RES MF 3.83K 1/10W 1% 0603; AGILE_PN: 470-76120; CAD_APPROVED: Yes; FPLIST: RC0603_OV,RC0603,0603_CC; HEIGHT: 0.55 MM; MFG_NAME01: KOA SPEER; MFG_PN01: RK73H1JTTD3831F; ROHS: Yes; Tolerance: 1%
R26 R30 R34 R52 = RES: RES MF 10K 1/10W 5% 0603; AGILE_PN: 470-75410; CAD_APPROVED: Yes; FPLIST: RC0603_OV,RC0603,0603_CC; HEIGHT: 0.55MM; MFG_NAME01: KOA SPEER; MFG_PN01: RK73B1JTTD103J; ROHS: Yes; Tolerance: 5%
R54 R57 R61 = RES: RES MF 2.2K 1/10W 5% 0603; AGILE_PN: 470-75399; CAD_APPROVED: Yes; FPLIST: RC0603_OV,RC0603,0603_CC; HEIGHT: 0.55MM; MFG_NAME01: VENKEL COMPANY; MFG_PN01: CR0603-10W-222JT; ROHS: Yes; Tolerance: 5%
R55 R58 R62 = RES: RES MF 2.2K 1/10W 5% 0603; AGILE_PN: 470-75399; ASSY_OPT: DNP; CAD_APPROVED: Yes; FPLIST: RC0603_OV,RC0603,0603_CC; HEIGHT: 0.55MM; MFG_NAME01: VENKEL COMPANY; MFG_PN01: CR0603-10W-222JT; ROHS: Yes; Tolerance: 5%
R59 R60 = RES: RES MF 2.2K 1/16W 1% 0402; AGILE_PN: 470-78359; CAD_APPROVED: Yes; FPLIST: RC0402_25,RC0402_HD,0402_CC; HEIGHT: 0.4MM; MFG_NAME01: KOA SPEER; MFG_PN01: RK73H1ETTP2201F; ROHS: Yes; Tolerance: 1%
SW5 = SW2P: SW SPST NO 0.05A 12V SMD; AGILE_PN: 510-77858; CAD_APPROVED: Yes; HEIGHT: 5.2 MM; MFG_NAME01: PANASONIC; MFG_PN01: EVQPE105K; ROHS: Yes
SW6-SW8 = SW2P: SW SPST NO 0.05A 12V SMD; AGILE_PN: 510-77858; ASSY_OPT: DNP; CAD_APPROVED: Yes; HEIGHT: 5.2 MM; MFG_NAME01: PANASONIC; MFG_PN01: EVQPE105K; ROHS: Yes
U5 = KL17Z64VF_QFN_32P_EP: IC MCU 64KB FLASH 48MHZ 1.71-3.6V QFN32; AGILE_PN: 344-02160; CAD_APPROVED: Yes; HEIGHT: 0.65 MM; MFG_NAME01: FREESCALE SEMICONDUCTOR; ROHS: Yes
U6 = Atmel_Serial_EEPROM_64K-1: IC MEM EEPROM 32KX8 1MHZ I2C 1.8-5.5V TSSOP-8; AGILE_PN: 334-30033; CAD_APPROVED: Yes; HEIGHT: 1.1MM; MFG_NAME01: MICROCHIP TECHNOLOGY INC; MFG_PN01: 24FC256-I/STG; ROHS: Yes
J5 = CONN_PCI_XPRESS_X16_328P: CON DUAL 2X82 Edge PCI Express SMT 1MM SP 591H FOR TOWER SYSTEM NOT A PART TO ORDER; AGILE_PN: 211-78844; CAD_APPROVED: Yes; HEIGHT: 15.01MM; MFG_NAME01: NA; MFG_PN01: EDGE PCI EXPRESS 164; ROHS: Yes
J6-J8 J13 J14 = CONN_HDR_3X2: HDR 2X3 TH 100MIL CTR 335H AU 95L; AGILE_PN: 210-75698; CAD_APPROVED: Yes; HEIGHT: 8.5MM; MFG_NAME01: SAMTEC; MFG_PN01: TSW-103-07-S-D; ROHS: Yes
JP5 JP11 = CONN_HDR_1X1: HDR 1X1 TH -- 330H AU 100L; AGILE_PN: 210-75767; ASSY_OPT: DNP; CAD_APPROVED: Yes; HEIGHT: 8.585 MM; MFG_NAME01: SAMTEC; MFG_PN01: HTSW-101-07-SM-S; ROHS: Yes
C10 = CAP_NP: CAP CER 2.2uF 25V 10% X7R 0805; AGILE_PN: 150-75638; CAD_APPROVED: Yes; FPLIST: CC0805_OV,CC0805,0805_CC; HEIGHT: 1.45MM; MFG_NAME01: AVX; MFG_PN01: 08053C225KAT2A; ROHS: Yes; TOL: 10%; Tolerance: 10%; VOLTAGE: 25V
C58 C59 = CAP_NP: CAP CER 22PF 50V 5% C0G 0402; AGILE_PN: 150-75266; CAD_APPROVED: Yes; FPLIST: CC0402_25,CC0402_HD,0402_CC; HEIGHT: 0.635MM; MFG_NAME01: AVX; MFG_PN01: 04025A220JAT2A; ROHS: Yes; Tolerance: 5%; VOLTAGE: 50V
C61 C75 = CAP_NP: CAP CER 10UF 10V 20% X5R 0603; AGILE_PN: 150-78609; CAD_APPROVED: Yes; FPLIST: CC0603_OV,CC0603,0603_CC; HEIGHT: 1.016MM; MFG_NAME01: TAIYO YUDEN; MFG_PN01: LMK107BJ106MALTD; ROHS: Yes; VOLTAGE: 10V
D50 = ZDIODE: DIODE ZNR 3W 5.6V -- REGULATOR SMB; AGILE_PN: 480-75211; CAD_APPROVED: YES; HEIGHT: 2.56 MM; MFG_NAME01: ON SEMICONDUCTOR; ROHS: Yes
F50 = FUSE: FUSE FAST 0.5A 32V SMT 0805; AGILE_PN: 510-75998; CAD_APPROVED: Yes; HEIGHT: 0.55 MM; MFG_NAME01: VISHAY INTERTECHNOLOGY; ROHS: Yes
J52 = USB_MINI_AB_RECEPTACLE: CON 5 USB_MINI_B_RECEPTACLE RA SMT 0.8MM 168H AU; AGILE_PN: 211-79254; CAD_APPROVED: Yes; HEIGHT: 4.27MM; MFG_NAME01: TE Connectivity Ltd; MFG_PN01: 1734035-2; ROHS: Yes
L50 L51 = BEAD: IND FER BEAD 330OHM@100MHZ 2.5A -- SMT; AGILE_PN: 180-30021; CAD_APPROVED: YES; HEIGHT: 1.05 MM; MFG_NAME01: TDK; MFG_PN01: MPZ2012S331A; PART_TYPE: FERRITE; ROHS: Yes; TOL: 25%; Tolerance: 25%
Q50 = NPN: TRAN NPN GEN SW 45V 0.1A SOT23; AGILE_PN: 480-78481; CAD_APPROVED: Yes; HEIGHT: 1.1MM; MFG_NAME01: NXP SEMICONDUCTORS; MFG_PN01: BC847C,215; ROHS: Yes
R50 = RES: RES MF ZERO OHM 1/16W -- AEC-Q200 0402; AGILE_PN: 470-80742; ASSY_OPT: DNP; CAD_APPROVED: Yes; FPLIST: RC0402_25,RC0402_HD,0402_CC; HEIGHT: 0.45 MM; MFG_NAME01: VISHAY INTERTECHNOLOGY; MFG_PN01: CRCW04020000Z0ED; ROHS: Yes
R51 R53 = RES: RES MF ZERO OHM 1/16W -- AEC-Q200 0402; AGILE_PN: 470-80742; CAD_APPROVED: Yes; FPLIST: RC0402_25,RC0402_HD,0402_CC; HEIGHT: 0.45 MM; MFG_NAME01: VISHAY INTERTECHNOLOGY; MFG_PN01: CRCW04020000Z0ED; ROHS: Yes
R56 = RES: RES MF 1.0M 1/10W 5% 0603; AGILE_PN: 470-75846; ASSY_OPT: DNP; CAD_APPROVED: Yes; FPLIST: RC0603_OV,RC0603,0603_CC; HEIGHT: 0.55MM; MFG_NAME01: KOA SPEER; MFG_PN01: RK73B1JTTD105J; ROHS: Yes; Tolerance: 5%
R63 R64 = RES: RES MF 33.0 OHM 1/16W 1% 0402; AGILE_PN: 470-75790; CAD_APPROVED: Yes; FPLIST: RC0402_25,RC0402_HD,RC0402_X2,0402_CC; HEIGHT: 0.4MM; MFG_NAME01: THYE MING TECH CO LTD; MFG_PN01: CR-02FL6---33R; ROHS: Yes; Tolerance: 1%
R65 = RES: RES MF 3.3K 1/10W 5% 0603; AGILE_PN: 470-75402; CAD_APPROVED: Yes; FPLIST: RC0603_OV,RC0603,0603_CC; HEIGHT: 0.6MM; MFG_NAME01: KOA SPEER; MFG_PN01: RK73B1JTTD332J; ROHS: Yes; Tolerance: 5%
R66 = RES: RES MF 33K 1/10W 1% 0603; AGILE_PN: 470-78066; CAD_APPROVED: Yes; FPLIST: RC0603_OV,RC0603,0603_CC; HEIGHT: 0.55MM; MFG_NAME01: KOA SPEER; MFG_PN01: RK73H1JTTD3302F; ROHS: Yes; Tolerance: 1%
TP13 = TestLoop: TEST POINT PC MULTI PURPOSE BLK TH; AGILE_PN: 210-79450; CAD_APPROVED: Yes; HEIGHT: 8.13MM; MFG_NAME01: KEYSTONE ELECTRONICS; MFG_PN01: 5011; ROHS: Yes; SILK: GND
TP16 = TestLoop: TEST POINT PC MULTI PURPOSE RED TH; AGILE_PN: 210-79454; CAD_APPROVED: Yes; HEIGHT: 8.13MM; MFG_NAME01: KEYSTONE ELECTRONICS; MFG_PN01: 5010; ROHS: Yes; SILK: P5V0_USB_CONN_VBUS
TP57 TP58 TP64 TP66-TP76 TP78 TP79 TP81 TP83-TP88 = TESTLOOP: TEST POINT PAD 30MIL DIA SMT, NO PART TO ORDER; AGILE_PN: 211-76642; CAD_APPROVED: Yes; HEIGHT: 0.1MM; MFG_NAME01: NOTACOMPONENT; MFG_PN01: NOTACOMPONENT; ROHS: Yes; SILK: PTE29
TP77 = TESTLOOP: TEST POINT PAD 30MIL DIA SMT, NO PART TO ORDER; AGILE_PN: 211-76642; CAD_APPROVED: Yes; HEIGHT: 0.1MM; MFG_NAME01: NOTACOMPONENT; MFG_PN01: NOTACOMPONENT; ROHS: Yes; SILK: P5V_KL25Z
TP80 = TESTLOOP: TEST POINT PAD 30MIL DIA SMT, NO PART TO ORDER; AGILE_PN: 211-76642; CAD_APPROVED: Yes; HEIGHT: 0.1MM; MFG_NAME01: NOTACOMPONENT; MFG_PN01: NOTACOMPONENT; ROHS: Yes; SILK: VREFH
TP82 = TESTLOOP: TEST POINT PAD 30MIL DIA SMT, NO PART TO ORDER; AGILE_PN: 211-76642; CAD_APPROVED: Yes; HEIGHT: 0.1MM; MFG_NAME01: NOTACOMPONENT; MFG_PN01: NOTACOMPONENT; ROHS: Yes; SILK: GND
TP89 = TESTLOOP: TEST POINT PAD 30MIL DIA SMT, NO PART TO ORDER; AGILE_PN: 211-76642; CAD_APPROVED: Yes; HEIGHT: 0.1MM; MFG_NAME01: NOTACOMPONENT; MFG_PN01: NOTACOMPONENT; ROHS: Yes; SILK: P3V3_KL25Z
TP90 = TESTLOOP: TEST POINT PAD 30MIL DIA SMT, NO PART TO ORDER; AGILE_PN: 211-76642; CAD_APPROVED: Yes; HEIGHT: 0.1MM; MFG_NAME01: NOTACOMPONENT; MFG_PN01: NOTACOMPONENT; ROHS: Yes; SILK: TC_USB_ID_TP
U7 = DIODE_2LINE_ESD: DIODE ESD 2LINE 5V SOT23; AGILE_PN: 480-78313; CAD_APPROVED: Yes; HEIGHT: 1.15MM; MFG_NAME01: VISHAY INTERTECHNOLOGY; ROHS: Yes
U50 = MKL25Z128VFT4_49P: IC MCU 128KB FLASH 16KB RAM 48MHZ 1.71-3.6V QFN48; AGILE_PN: 344-01428; CAD_APPROVED: Yes; HEIGHT: 1 MM; MFG_NAME01: Freescale Semiconductor; ROHS: Yes
U51 = LD1117AS18: IC VREG LDO 1A 3.3V SOT223; AGILE_PN: 312-80039; CAD_APPROVED: Yes; HEIGHT: 1.8MM; MFG_NAME01: ON Semiconductor; ROHS: Yes
U52 U53 = ADP172_CSP_4P: IC LOAD SW 0.5A 1.1-3.6V WLCSP4; AGILE_PN: 315-80702; CAD_APPROVED: Yes; HEIGHT: 0.54MM; MFG_NAME01: NXP SEMICONDUCTORS; MFG_PN01: NX3P190UK,012; ROHS: Yes
Y50 = CRYSTAL_JXS63: XTAL 8MHZ 20PPM PAR 18PF ESR 200OHM SMT; AGILE_PN: 230-77754; CAD_APPROVED: Yes; HEIGHT: 1.1MM; MFG_NAME01: Abracon Corporation; MFG_PN01: ABM3B-8.000MHZ-B2-T; ROHS: Yes

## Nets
3V3: C50.1 C51.1 C52.1 C53.1 C56.1 C57.1 C65.1 C66.1 C67.1 C68.1 C70.1 C71.1 J15.1(A1) R23.2 R26.1 R30.1 R36.2 R37.2 R38.2 R39.2 R48.2 R55.1 R58.1 R59.1 R60.1 R62.1 R67.2 U5.7(VDDA/VREFH) U5.15(VDD) U6.8(VCC) U8.13(VDDD) U8.14(VDDA) U9.13(VDDD) U9.14(VDDA) U52.A2(VOUT) U53.A2(VOUT)
3V3_LDO: C75.1 R65.1 U51.2(VOUT) U51.4(TAB) U52.A1(VIN)
5V: J5.A1(5V_2) J5.B1(5V_1) J5.C1(5V_4) J5.D1(5V_3)
24V: C19.1 C20.1 C21.1 C22.1 C24.1 C25.1 C26.1 C27.1 D12.C J18.2 J19.2 J20.2 J21.2 R21.1 R40.1 R41.1 R42.1 R43.1 U8.22(VCC) U9.22(VCC)
GND: C5.2 C6.2 C7.2 C8.2 C9.2 C10.2 C11.2 C12.2 C13.2 C14.2 C15.1 C16.2 C17.2 C18.2 C23.2 C24.2 C25.2 C26.2 C27.2 C28.2 C29.2 C30.2 C50.2 C51.2 C52.2 C53.2 C54.2 C55.2 C56.2 C57.2 C58.2 C59.2 C60.2 C61.2 C65.2 C66.2 C67.2 C68.2 C70.2 C71.2 C75.2 D5.C(CATHODE) D6.C(CATHODE) D7.C(CATHODE) D8.A D11.A D17.A D20.A D50.A(ANODE) J5.A2(GND_9) J5.A5(GND_10) J5.A6(GND_11) J5.A26(GND_12) J5.A31(GND_13) J5.A49(GND_14) J5.A65(GND_15) J5.A81(GND_16) J5.B2(GND_1) J5.B5(GND_2) J5.B6(GND_3) J5.B26(GND_4) J5.B31(GND_5) J5.B49(GND_6) J5.B65(GND_7) J5.B81(GND_8) J5.C2(GND_25) J5.C5(GND_26) J5.C6(GND_27) J5.C26(GND_28) J5.C31(GND_29) J5.C49(GND_30) J5.C65(GND_31) J5.C81(GND_32) J5.D2(GND_17) J5.D5(GND_18) J5.D6(GND_19) J5.D26(GND_20) J5.D31(GND_21) J5.D49(GND_22) J5.D65(GND_23) J5.D81(GND_24) J9.4 J9.5 J10.3 J11.3 J12.4 J12.5 J15.3(A2) J15.5(A3) J16.3 J17.2 J17.3 J22.4 J22.5 J23.3 J24.3 J25.4 J25.5 J52.5(P5) J53.3(A2) J53.5(A3) JP5.1 JP6.1 JP7.1 JP8.1 JP9.1 JP10.1 JP11.1 L51.2 Q50.2(EMITTER) R32.2 R47.1 R49.1 R54.2 R57.2 R61.2 SW5.2(NO) SW6.2(NO) SW7.2(NO) SW8.2(NO) TP13.1(Pin1) TP82.1(Pin1) U5.8(VREFL/VSSA) U5.16(VSS) U5.33(EP_PAD) U6.4(GND) U7.3(COM_ANODE) U8.15(GND) U8.30(LM2) U8.31(LM1) U8.39(LGND) U8.47(TP1) U8.49(EPAD) U9.15(GND) U9.30(LM2) U9.31(LM1) U9.39(LGND) U9.47(TP1) U9.49(EPAD) U50.2(VSS1) U50.11(VREFL) U50.12(VSSA) U50.23(VSS2) U50.49(EX_PAD) U51.1(GND) U52.B2(GND) U53.B2(GND) Y5.2 Y5.4 Y50.2(GND1) Y50.4(GND2)
P3V3_KL25Z: C9.1 C10.1 C11.1 C12.1 C13.1 C14.1 C17.1 C18.1 J53.1(A1) R19.2 R34.1 R52.1 R53.2 TP89.1(Pin1) U50.1(VDD1) U50.5(VOUT33) U50.9(VDDA) U50.22(VDD2)
P5V0_USB_CONN_VBUS: F50.1 J52.1(P1) TP16.1(Pin1)
P5V_USB: C60.1 C61.1 L50.2 TP77.1(Pin1) U50.6(VREGIN) U51.3(VIN)
VDDA: J5.A46(VDDA)
VSSA: J5.A45(VSSA)
BOOT_MCU: C7.1 R30.2 SW6.1(COMMON) TP11.1(Pin1) U5.14(PTA4/~{NMI}/I2C1_SDA/TPM0_CH1)
CLK_Master: U8.43(XTAL1) U9.12(CLK)
CONV_CLK: J7.6(B3) U50.46(PTD5/ADC0_SE6B/SPI1_SCK/UART2_TX/TPM0_CH5)
CONV_CS0: J8.6(B3) R50.2 R51.2
CONV_INT: J13.6(B3) U50.42(PTD1/ADC0_SE5B/SPI0_SCK/TPM0_CH1)
CONV_MISO: J6.6(B3) U50.48(PTD7/SPI1_MISO/UART0_TX/SPI1_MOSI)
CONV_MOSI: J14.6(B3) U50.47(PTD6/LLWU_P15/ADC0_SE7B/SPI1_MOSI/UART0_RX/SPI1_MISO)
EE_ADDR0: R54.1 R55.2 U6.1(A0)
EE_ADDR1: R57.1 R58.2 U6.2(A1)
EE_ADDR2: R61.1 R62.2 U6.3(A2)
EEPROM_SCL: J16.2 R33.2 U5.20(PTB0/LLWU_P5/ADC0_SE8/I2C0_SCL/TPM1_CH0/SPI1_MOSI/SPI1_MISO)
EEPROM_SDA: J16.1 R35.2 U5.21(PTB1/ADC0_SE9/I2C0_SDA/TPM1_CH1/SPI1_MISO/SPI1_MOSI)
KL25Z_BOOT_ACTIVATE: C54.1 R52.2 SW7.1(COMMON) U50.27(PTB0/LLWU_P5/ADC0_SE8/TSI0_CH0/I2C0_SCL/TPM1_CH0)
MS1_CQ1: D10.A D11.C J11.2 J12.3 U9.33(CQ1)
MS1_CQ2: D19.A D20.C J23.2 J25.3 U9.28(CQ2)
MS1_GATE1: R25.2 TP15.1(Pin1) U9.38(GATE1)
MS1_GATE2: R44.2 TP18.1(Pin1) U9.37(GATE2)
MS1_INTX: JP8.6 U5.11(PTA1/LPUART0_RX/TPM2_CH0) U9.6(INTX)
MS1_LP1: C6.1 D10.C J11.1 J12.2 Q5.4(SOURCE1) Q5.8(SOURCE2) R28.1 U9.35(LP1)
MS1_LP2: C28.1 D19.C J23.1 J25.2 Q7.4(SOURCE1) Q7.8(SOURCE2) R45.1 U9.26(LP2)
MS1_MISO: JP8.2 U5.28(PTC7/CMP0_IN1/SPI0_MISO/SPI0_MOSI) U9.10(MISO)
MS1_MOSI: JP8.3 U5.27(PTC6/LLWU_P10/CMP0_IN0/SPI0_MOSI/EXTRG_IN/SPI0_MISO) U9.9(MOSI)
MS1_RXD1: JP10.9 U9.1(RXD1/CYCT1)
MS1_RXD2: JP10.5 U9.16(RXD2/CYCT2)
MS1_SCLK: JP8.4 U5.26(PTC5/LLWU_P9/SPI0_SCK/LPTMR0_ALT2/CMP0_OUT) U9.8(SCLK)
MS1_SDX1: JP10.6 U5.1(PTE0/CLKOUT32K/SPI1_MISO/LPUART1_TX/RTC_CLKOUT/CMP0_OUT/I2C1_SDA) U9.4(SDX1)
MS1_SDX2: JP10.2 U5.2(PTE1/SPI1_MOSI/LPUART1_RX/SPI1_MISO/I2C1_SCL) U9.19(SDX2)
MS1_SEN1: C22.2 J21.1 Q5.1(DRAIN1) Q5.2(DRAIN2) Q5.5(DRAIN3) Q5.6(DRAIN4) Q5.7(DRAIN5) R28.2 R43.2 U9.23(SEN1)
MS1_SEN2: C21.2 J20.1 Q7.1(DRAIN1) Q7.2(DRAIN2) Q7.5(DRAIN3) Q7.6(DRAIN4) Q7.7(DRAIN5) R42.2 R45.2 U9.24(SEN2)
MS1_SSX: JP8.5 U5.25(PTC4/LLWU_P8/SPI0_PCS0/LPUART1_TX/TPM0_CH3/SPI1_PCS0) U9.7(SSX)
MS1_SSX1: TP9.1(Pin1) U5.24(PTC3/LLWU_P7/SPI1_SCK/LPUART1_RX/TPM0_CH2/CLKOUT)
MS1_TEMP: TP21.1(Pin1) U9.46(TEMP)
MS1_TXD1: JP10.7 U9.2(TXD1/SYNC1)
MS1_TXD2: JP10.3 U9.17(TXD2/SYNC2)
MS1_TXEN1: JP10.8 U9.3(TXEN1)
MS1_TXEN2: JP10.4 U9.18(TXEN2)
MS2_CQ1: D8.C D9.A J9.3 J10.2 U8.33(CQ1)
MS2_CQ2: D17.C D18.A J22.3 J24.2 U8.28(CQ2)
MS2_GATE1: R31.2 TP14.1(Pin1) U8.38(GATE1)
MS2_GATE2: R68.2 TP17.1(Pin1) U8.37(GATE2)
MS2_INTX: JP7.6 U5.12(PTA2/LPUART0_TX/TPM2_CH1) U8.6(INTX)
MS2_LP1: C8.1 D9.C J9.2 J10.1 Q6.4(SOURCE1) Q6.8(SOURCE2) R29.1 U8.35(LP1)
MS2_LP2: C30.1 D18.C J22.2 J24.1 Q8.4(SOURCE1) Q8.8(SOURCE2) R46.1 U8.26(LP2)
MS2_MISO: JP7.2 U5.32(PTD7/SPI1_MISO/LPUART0_TX/2C1_SCL/SPI1_MOSI/FXIO0_D7) U8.10(MISO)
MS2_MOSI: JP7.3 U5.31(PTD6/LLWU_P15/ADC0_SE7B/SPI1_MOSI/LPUART0_RX/I2C1_SDA/SPI1_MISO/FXIO0_D6) U8.9(MOSI)
MS2_RXD1: JP9.9 U8.1(RXD1/CYCT1)
MS2_RXD2: JP9.5 U8.16(RXD2/CYCT2)
MS2_SCLK: JP7.4 U5.30(PTD5/ADC0_SE6B/SPI1_SCK/UART2_TX/TPM0_CH5/FXIO0_D5) U8.8(SCLK)
MS2_SDX1: JP9.6 U5.22(PTC1/LLWU_P6/RTC_CLKIN/ADC0_SE15/I2C1_SCL/TPM0_CH0) U8.4(SDX1)
MS2_SDX2: JP9.2 U5.23(PTC2/ADC0_SE11/I2C1_SDA/TPM0_CH1) U8.19(SDX2)
MS2_SEN1: C20.2 J19.1 Q6.1(DRAIN1) Q6.2(DRAIN2) Q6.5(DRAIN3) Q6.6(DRAIN4) Q6.7(DRAIN5) R29.2 R41.2 U8.23(SEN1)
MS2_SEN2: C19.2 J18.1 Q8.1(DRAIN1) Q8.2(DRAIN2) Q8.5(DRAIN3) Q8.6(DRAIN4) Q8.7(DRAIN5) R40.2 R46.2 U8.24(SEN2)
MS2_SSX: JP7.5 U5.29(PTD4/LLWU_P14/SPI1_PCS0/UART2_RX/TPM0_CH4/FXI00_D4) U8.7(SSX)
MS2_TEMP: TP20.1(Pin1) U8.46(TEMP)
MS2_TXD1: JP9.7 U8.2(TXD1/SYNC1)
MS2_TXD2: JP9.3 U8.17(TXD2/SYNC2)
MS2_TXEN1: JP9.8 U8.3(TXEN1)
MS2_TXEN2: JP9.4 U8.18(TXEN2)
RST_KL25Z: C16.1 J53.10(B5) R34.2 SW8.1(COMMON) TP12.1(Pin1) U50.26(PTA20/~{RESET})
RST_MCU: C5.1 J15.10(B5) R26.2 SW5.1(COMMON) TP8.1(Pin1) U5.19(PTA20/~{RESET})
SHIELD_K20USB: J52.S1(SHLD1) J52.S2(SHLD2) J52.S3(SHLD3) J52.S4(SHLD4) L51.1
SPI0_CLK: J5.B48(SPI0_CLK) R14.2
SPI0_CS0: J5.B46(~{SPI0_CS0}) R20.2
SPI0_CS1: J5.B47(~{SPI0_CS1}) R16.2
SPI0_MISO: J5.B44(SPI0_MISO/IO1) R13.2
SPI0_MOSI: J5.B45(SPI0_MOSI/IO0) R17.2
SPI1_CLK: J5.B7(SDHC_CLK/SPI1_CLK) J7.4(B2)
SPI1_CS0: J5.B9(SDHC_D3/~{SPI1_CS0}) J8.4(B2)
SPI1_CS1: J5.B8(SDHC_D3/~{SPI1_CS1}) R18.2
SPI1_MISO: J5.B11(SDHC_D0/SPI1_MISO) J6.4(B2)
SPI1_MOSI: J5.B10(SDHC_CMD/SPI1_MOSI) J14.4(B2)
SPI2_CLK: J5.D7(SPI2_CLK) R15.2
SPI2_CS0: J5.D9(~{SPI2_CS0}) R24.2
SPI2_CS1: J5.D8(~{SPI2_CS1}) R22.2
SPI2_MISO: J5.D11(SPI2_MISO) R12.2
SPI2_MOSI: J5.D10(SPI2_MOSI) R27.2
SWD_CLK: J15.4(B2) U5.10(PTA0/SWD_CLK/TPM0_CH5)
SWD_CLK_KL25Z: J53.4(B2) U50.17(PTA0/SWD_CLK/TSI0_CH1/TPM0_CH5)
SWD_DIO: J15.2(B1) U5.13(PTA3/SWD_DIO/I2C1_SCL/TPM0_CH0)
SWD_DIO_KL25Z: J53.2(B1) U50.20(PTA3/SWD_DIO/TSI0_CH4/I2C1_SCL/TPM0_CH0)
TC_USB_ID_TP: J52.4(P4) TP90.1(Pin1)
TWR_3V3: J5.A3(3.3V_4) J5.A4(3.3V_5) J5.A36(3.3V_6) J5.A82(3.3V_7) J5.B3(3.3V_1) J5.B36(3.3V_2) J5.B82(3.3V_3) J5.C3(3.3V_11) J5.C4(3.3V_12) J5.C36(3.3V_13) J5.C82(3.3V_14) J5.D3(3.3V_8) J5.D36(3.3V_9) J5.D82(3.3V_10) R66.1 U53.A1(VIN) U53.B1(EN)
TWR_CLK: J7.1(A1) J7.3(A2) J7.5(A3) JP6.5 U5.4(PTE17/ADC0_DM1/ADC0_SE5A/SPI0_SCK/UART2_RX/TPM_CLKIN1/LPTMR0_ALT3/FXIO0_D1)
TWR_CS0: J8.1(A1) J8.3(A2) J8.5(A3) JP6.6 U5.3(PTE16/ADC0_DP1/ADC0_SE1/SPI0_PCS0/UART2_TX/TPM_CLKIN0/FXI00_D0)
TWR_INT: J13.1(A1) J13.3(A2) J13.5(A3) JP6.2 U5.9(PTE30/ADC0_SE23/CMP0_IN4/TPM0_CH3/TPM_CLKIN1/LPUART1_TX/LPTMR0_ALT1/~{VREF0})
TWR_INT_1: R7.2 R8.1
TWR_INT_2: J13.4(B2) R9.1
TWR_INT_3: R6.2 R10.1
TWR_INT_4: R5.2 R11.1
TWR_MISO: J6.1(A1) J6.3(A2) J6.5(A3) JP6.3 U5.6(PTE19/ADC0_DM2/ADC0_SE6A/SPI0_MISO/I2C0_SCL/SPI0_MOSI/FXIO0_D3)
TWR_MOSI: J14.1(A1) J14.3(A2) J14.5(A3) JP6.4 U5.5(PTE18/ADC0_DP2/ADC0_SE2/SPI0_MOSI/I2C0_SDA/SPI0_MISO/FXIO0_D2)
USB_CONN_DN: J52.2(P2) R64.1 U7.1(CATHODE1)
USB_CONN_DP: J52.3(P3) R63.1 U7.2(CATHODE2)
USB_DM: R64.2 U50.4(USB0_DM)
USB_DP: R63.2 U50.3(USB0_DP)
VREFH: C15.2 C55.1 R53.1 TP80.1(Pin1) U50.10(VREFH)
N51941022: R35.1 R60.2 U6.5(SDA)
N51941025: R33.1 R59.2 U6.6(SCL)
N51968614: D15.C(CATHODE) U9.41(LED1)
N51968623: D16.C(CATHODE) U9.40(LED2)
N51972698: C29.1 U9.44(XTAL2) Y5.3
N51980032: R32.1 U6.7(WP)
N51981285: D7.A(ANODE) R23.1
N51981437: D6.A(ANODE) R21.2
N51981716: D16.A(ANODE) R39.1
N51981719: D15.A(ANODE) R38.1
N51986239: R49.2 R67.1 U9.48(CLK_EN)
N52006957: J8.2(B1) R16.1 R18.1 R20.1 R22.1 R24.1
N52007703: J5.B60(IRQ_C) R9.2
N52007706: J5.B62(IRQ_A) R8.2
N52011483: R47.2 R48.1 U8.48(CLK_EN)
N52011777: D13.C(CATHODE) U8.41(LED1)
N52011781: D14.C(CATHODE) U8.40(LED2)
N52011843: D14.A(ANODE) R37.1
N52011845: D13.A(ANODE) R36.1
N52039256: J5.B56(IRQ_G) R11.2
N52039259: J5.B58(IRQ_E) R10.2
N52039370: J13.2(B1) R5.1 R6.1 R7.1
N52105751: Q50.3(COLLECTOR) R65.2 U52.B1(EN)
N52105774: Q50.1(BASE) R66.2
N52116188: C23.1 U9.43(XTAL1) Y5.1
N52149421: J25.1 TP22.1(Pin1)
N52149434: J12.1 TP10.1(Pin1)
N52149447: J22.1 TP19.1(Pin1)
N52149460: J9.1 TP5.1(Pin1)
N52159106: Q6.3(GATE1) R31.1
N52159127: Q8.3(GATE1) R68.1
N52159490: D12.A J17.1(Pin)
N52178619: Q7.3(GATE1) R44.1
N52178906: Q5.3(GATE1) R25.1
N52281250: J6.2(B1) R12.1 R13.1
N52284736: D50.C(CATHODE) F50.2 L50.1
N52285941: C59.1 R56.1 U50.24(PTA18/EXTAL0/UART1_RX/TPM_CLKIN0) Y50.1
N52286024: C58.1 R56.2 U50.25(PTA19/XTAL0/UART1_TX/TPM_CLKIN1/LPTMR0_ALT1) Y50.3
N52286041: R51.1 U50.44(PTD3/SPI0_MISO/UART2_TX/TPM0_CH3/SPI0_MOSI)
N52290882: TP83.1(Pin1) U50.13(PTE29/CMP0_IN5/ADC0_SE4B/TPM0_CH2/TPM_CLKIN0)
N52290920: TP78.1(Pin1) U50.28(PTB1/ADC0_SE9/TSI0_CH6/I2C0_SDA/TPM1_CH1)
N52290933: TP76.1(Pin1) U50.29(PTB2/ADC0_SE12/TSI0_CH7/I2C0_SCL/TPM2_CH0)
N52290949: TP75.1(Pin1) U50.30(PTB3/ADC0_SE13/TSI0_CH8/I2C0_SDA/TPM2_CH1)
N52290962: TP74.1(Pin1) U50.31(PTB16/TSI0_CH9/SPI1_MOSI/UART0_RX/TPM_CLKIN0/SPI1_MISO)
N52290975: TP73.1(Pin1) U50.32(PTB17/TSI0_CH10/SPI1_MISO/UART0_TX/TPM_CLKIN1/SPI1_MOSI)
N52291034: TP72.1(Pin1) U50.33(PTC0/ADC0_SE14/TSI0_CH13/EXTRG_IN/CMP0_OUT)
N52291047: TP67.1(Pin1) U50.34(PTC1/LLWU_P6/RTC_CLKIN/ADC0_SE15/TSI0_CH14/I2C1_SCL/TPM0_CH0)
N52291060: TP71.1(Pin1) U50.35(PTC2/ADC0_SE11/TSI0_CH15/I2C1_SDA/TPM0_CH1)
N52291085: TP66.1(Pin1) U50.36(PTC3/LLWU_P7/UART1_RX/TPM0_CH2/CLKOUT)
N52291099: TP70.1(Pin1) U50.37(PTC4/LLWU_P8/SPI0_PCS0/UART1_TX/TPM0_CH3)
N52291114: TP64.1(Pin1) U50.38(PTC5/LLWU_P9/SPI0_SCK/LPTMR0_ALT2/CMP0_OUT)
N52291127: TP69.1(Pin1) U50.39(PTC6/LLWU_P10/CMP0_IN0/SPI0_MOSI/EXTRG_IN/SPI0_MISO)
N52291143: TP58.1(Pin1) U50.40(PTC7/CMP0_IN1/SPI0_MISO/SPI0_MOSI)
N52291156: TP84.1(Pin1) U50.15(PTE24/TPM0_CH0/I2C0_SCL)
N52291179: TP68.1(Pin1) U50.41(PTD0/SPI0_PCS0/TPM0_CH0)
N52291192: TP57.1(Pin1) U50.43(PTD2/SPI0_MOSI/UART2_RX/TPM0_CH2/SPI0_MISO)
N52291212: R50.1 U50.45(PTD4/LLWU_P14/SPI1_PCS0/UART2_RX/TPM0_CH4)
N52302946: TP6.1(Pin1) U5.17(PTA18/EXTAL0/LPUART1_RX/TPM_CLKIN0)
N52302949: TP7.1(Pin1) U5.18(PTA19/XTAL0/LPUART1_TX/TPM_CLKIN1/LPTMR0_ALT1)
N52312996: J14.2(B1) R17.1 R27.1
N52313183: J7.2(B1) R14.1 R15.1
N52316776: D5.A(ANODE) R19.1
N52354543: TP85.1(Pin1) U50.18(PTA1/TSI0_CH2/UART0_RX/TPM2_CH0)
N52354544: TP87.1(Pin1) U50.14(PTE30/DAC0_OUT/ADC0_SE23/CMP0_IN4/TPM0_CH3/TPM_CLKIN1)
N52354545: TP81.1(Pin1) U50.8(PTE21/ADC0_DM0/ADC0_SE4A/TPM1_CH1/UART0_RX)
N52354546: TP79.1(Pin1) U50.7(PTE20/ADC0_DP0/ADC0_SE0/TPM1_CH0/UART0_TX)
N52354547: TP86.1(Pin1) U50.21(PTA4/~{NMI}/TSI0_CH5/I2C1_SDA/TPM0_CH1)
N52354548: TP88.1(Pin1) U50.16(PTE25/TPM0_CH1/I2C0_SDA)

Not connected (* = marked no-connect by the designer): J5 A7(I2C0_SCL)* A8(I2C0_SDA)* A9(GPIO9/UART1_CTS)* A10(GPIO8/SDHC_D2)* A11(GPIO7/SD_WP_DET)* A12(ETH_CRS)* A13(ETH_MDC_1)* A14(ETH_MDIO_1)* A15(ETH_RXCLK_1)* A16(ETH_RXDV_1)* A17(ETH_RXD3)* A18(ETH_RXD2)* A19(ETH_RXD1_1)* A20(ETH_RXD0_1)* A21(I2S0_MCLK)* A22(I2S0_DOUT_SCK)* A23(I2S0_DOUT_WS)* A24(I2S0_DIN0)* A25(I2S0_DOUT0)* A27(AN3)* A28(AN2)* A29(AN1)* A30(AN0)* A32(DAC0)* A33(TMR1)* A34(TMR0)* A35(GPIO6)* A37(PWM3)* A38(PWM2)* A39(PWM1)* A40(PWM0)* A41(UART0_RX)* A42(UART0_TX)* A43(UART1_RX)* A44(UART1_TX)* A47(CAN1_RX)* A48(CAN1_TX)* A50(GPIO14)* A51(GPIO15)* A52(GPIO16/SPI0_WP/IO2)* A53(GPIO17)* A54(USB0_DM)* A55(USB0_DP)* A56(USB0_ID)* A57(USB0_VBUS)* A58(I2S0_DIN_SCK)* A59(I2S0_DIN_WS)* A60(I2S0_DIN1)* A61(I2S0_DOUT1)* A62(~{RSTIN})* A63(~{RSTOUT})* A64(CLKOUT0)* A66(EBI_AD14)* A67(EBI_AD13)* A68(EBI_AD12)* A69(EBI_AD11)* A70(EBI_AD10)* A71(EBI_AD9)* A72(EBI_AD8)* A73(EBI_AD7)* A74(EBI_AD6)* A75(EBI_AD5)* A76(EBI_AD4)* A77(EBI_AD3)* A78(EBI_AD2)* A79(EBI_AD1)* A80(EBI_AD0)* B4(ELE_PS_SENSE_1)* B12(ETH_COL_1)* B13(ETH_RXER_1)* B14(ETH_TXCLK_1)* B15(ETH_TXEN_1)* B16(ETH_TXER)* B17(ETH_TXD3)* B18(ETH_TXD2)* B19(ETH_TXD1_1)* B20(ETH_TXD0_1)* B21(GPIO1/UART1_RTS)* B22(GPIO2/SDHC_D1)* B23(GPIO3)* B24(CLKIN0)* B25(CLKOUT1)* B27(AN7)* B28(AN6)* B29(AN5)* B30(AN4)* B32(DAC1)* B33(TMR3)* B34(TMR2)* B35(GPIO4)* B37(PWM7)* B38(PWM6)* B39(PWM5)* B40(PWM4)* B41(CAN0_RX)* B42(CAN0_TX)* B43(1WIRE)* B50(I2C1_SCL)* B51(I2C1_SDA)* B52(GPIO5/SPI0_HOLD/IO3)* B53(RSRV)* B54(RSRV)* B55(IRQ_H)* B57(IRQ_F)* B59(IRQ_D)* B61(IRQ_B)* B63(EBI_ALE/~{EBI_CS1})* B64(~{EBI_CS0})* B66(EBI_AD15)* B67(EBI_AD16)* B68(EBI_AD17)* B69(EBI_AD18)* B70(EBI_AD19)* B71(EBI_R/~{W})* B72(~{EBI_OE})* B73(EBI_D7)* B74(EBI_D6)* B75(EBI_D5)* B76(EBI_D4)* B77(EBI_D3)* B78(EBI_D2)* B79(EBI_D1)* B80(EBI_D0)* C7(I2C2_SCL)* C8(I2C2_SDA)* C9(GPIO25)* C10(ULPI_STOP)* C11(ULPI_CLK)* C12(GPIO26)* C13(ETH_MDC_2)* C14(ETH_MDIO_2)* C15(ETH_RXCLK_2)* C16(ETH_RXDV_2)* C17(GPIO27/SDHC_D6)* C18(GPIO28/SDHC_D7)* C19(ETH_RXD1_2)* C20(ETH_RXD0_2)* C21(ULPI_DATA0/I2S1_MCLK)* C22(ULPI_DATA1/I2S1_DOUT_SCK)* C23(ULPI_DATA2/I2S1_DOUT_WS)* C24(ULPI_DATA3/I2S1_DIN0)* C25(ULPI_DATA4/I2S1_DOUT0)* C27(AN11)* C28(AN10)* C29(AN9)* C30(AN8)* C32(GPIO29/UART2_DCD)* C33(TMR9)* C34(TMR8)* C35(GPIO30/UART3_DCD)* C37(PWM11)* C38(PWM10)* C39(PWM9)* C40(PWM8)* C41(UART2_RXD/TSI0)* C42(UART2_TXD/TSI1)* C43(UART2_RTS/TSI2)* C44(UART2_CTS/TSI3)* C45(UART3_RXD/TSI4)* C46(UART3_TXD/TSI5)* C47(UART3_RTS/CAN3_RX)* C48(UART3_CTS/CAN3_TX)* C50(LCD_D4/LCD_P4)* C51(LCD_D5/LCD_P5)* C52(LCD_D6/LCD_P6)* C53(LCD_D7/LCD_P7)* C54(LCD_D8/LCD_P8)* C55(LCD_D9/LCD_P9)* C56(LCD_D10/LCD_P10)* C57(LCD_D11/LCD_P11)* C58(I2S1_DIN_SCK)* C59(I2S1_DIN_WS)* C60(I2S1_DIN1)* C61(I2S1_DOUT1)* C62(LCD_D15/LCD_P15)* C63(LCD_D16/LCD_P16/SD_GND)* C64(LCD_D17/LCD_P17/SD_GND)* C66(~{EBI_BE_32_24}/LCD_P28/SD_TX_0+)* C67(~{EBI_BE_23_16}/LCD_P29/SD_TX_0-)* C68(~{EBI_BE_15_8}/LCD_P30/SD_GND)* C69(~{EBI_BE_7_0}/LCD_P31/SD_GND)* C70(EBI_TSIZE0/LCD_P32/SD_TX_1+)* C71(EBI_TSIZE1/LCD_P33/SD_TX_1-)* C72(~{EBI_TS}/LCD_P34/SD_GND)* C73(~{EBI_TBST}/LCD_P35/SD_GND)* C74(~{EBI_TA}/LCD_P36/SD_TX_2+)* C75(~{EBI_CS4}/LCD_P37/SD_TX_2-)* C76(~{EBI_CS3}/LCD_P38/SD_GND)* C77(~{EBI_CS2}/LCD_P39/SD_GND)* C78(~{EBI_CS1}/LCD_P40/SD_TX_3+)* C79(GPIO31/LCD_P41/SD_TX_3-)* C80(LCD_D23/LCD_P23/SD_GND)* D4(ELE_PS_SENSE_2)* D12(ETH_COL_2)* D13(ETH_RXER_2)* D14(ETH_TXCLK_2)* D15(ETH_TXEN_2)* D16(GPIO18)* D17(GPIO19/SDHC_D4)* D18(GPIO20/SDHC_D5)* D19(ETH_TXD1_2)* D20(ETH_TXD0_2)* D21(ULPI_NEXT/USB_HS_DM)* D22(ULPI_DIR/USB_HS_DP)* D23(UPLI_DATA5/USB_HS_VBUS)* D24(ULPI_DATA6/USB_HS_ID)* D25(ULPI_DATA7)* D27(LCD_HSYNC/LCD_P24)* D28(LCD_VSYNC/LCD_P25)* D29(AN13)* D30(AN12)* D32(LCD_CLK/LCD_P26)* D33(TMR11)* D34(TMR10)* D35(GPIO21)* D37(PWM15)* D38(PWM14)* D39(PWM13)* D40(PWM12)* D41(CAN2_RX)* D42(CAN2_TX)* D43(LCD_CONTRAST)* D44(LCD_OE/LCD_P27)* D45(LCD_D0/LCD_P0)* D46(LCD_D1/LCD_P1)* D47(LCD_D2/LCD_P2)* D48(LCD_D3/LCD_P3)* D50(GPIO23)* D51(GPIO24)* D52(LCD_D12/LCD_P12)* D53(LCD_D13/LCD_P13)* D54(LCD_D14/LCD_P14)* D55(IRQ_P/~{SPI2_CS2})* D56(IRQ_O/~{SPI2_CS3})* D57(IRQ_N)* D58(IRQ_M)* D59(IRQ_L)* D60(IRQ_K)* D61(IRQ_J)* D62(IRQ_I)* D63(LCD_D18/LCD_P18/SD_RX_0+)* D64(LCD_D19/LCD_P19/SD_RX_0-)* D66(EBI_AD20/LCD_P42/SD_GND)* D67(EBI_AD21/LCD_P43/SD_GND)* D68(EBI_AD22/LCD_P44/SD_RX_1+)* D69(EBI_AD23/LCD_P45/SD_RX_1-)* D70(EBI_AD24/LCD_P46/SD_GND)* D71(EBI_AD25/LCD_P47/SD_GND)* D72(EBI_AD26/LCD_P48/SD_RX_2+)* D73(EBI_AD27/LCD_P49/SD_RX_2-)* D74(EBI_AD28/LCD_P50/SD_GND)* D75(EBI_AD29/LCD_P51/SD_GND)* D76(EBI_AD30/LCD_P52/SD_RX_3+)* D77(EBI_AD31/LCD_P53/SD_RX_3-)* D78(LCD_D20/LCD_P20/SD_GND)* D79(LCD_D21/LCD_P21/SD_REFCLK+)* D80(LCD_D22/LCD_P22/SD_REFCLK-)*; J15 6(B3)* 7(A4)* 8(B4)* 9(A5)*; J53 6(B3)* 7(A4)* 8(B4)* 9(A5)*; U8 5(NC)* 11(NC)* 12(CLK)* 20(TP2)* 21(NC)* 25(NC)* 27(NC)* 29(NC)* 32(NC)* 34(NC)* 36(NC)* 42(NC)* 44(XTAL2)* 45(NC)*; U9 5(NC)* 11(NC)* 20(TP2)* 21(NC)* 25(NC)* 27(NC)* 29(NC)* 32(NC)* 34(NC)* 36(NC)* 42(NC)* 45(NC)*; U50 19(PTA2/TSI0_CH3/UART0_TX/TPM2_CH1)*

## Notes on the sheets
sheet 2
- Table of Contents
- Revisions
- 1
- TITLE, TOC & REV
- Rev
- Description
- Date
- Approved
- 2
- NOTES
- X1
- Original Release
- 14-JUN-15
- Tomas Marek
- 3
- IO link - Master
- A
- Prototype Manufacturing Release
- 23-SEP-15
- Tomas Marek
- 4
- MCU_KL17
- B
- BOM CHANGES
- 12-MAY-16
- Tomas Marek
- 5
- MCU_KL28
- 6
- Elevator Connectors
- TWR-CM3120-EVM
sheet 3
- IO-Link MASTER 1
- IO-Link MASTER 2
- CAD NOTE:
  Place these capacitors
  near their respective
  VDDD and VDDA pins.
- CAD NOTE:
  Place these capacitors
  near their respective
  VDDD and VDDA pins.
- Current Sense
- CLK output will be used
  to supply other Master device.
- Current Sense
- CLK is taken from the other
  Master device.
- IO-Link Channel 1 and 2
- M12 Connectors
- IO-Link Channel 2 and 3
- M12 Connectors
- Channel Protection
- Channel Protection
- IO-Link 3
- IO-Link 1
- IO-Link 4
- IO-Link 2
- MOSFETs
- MOSFETs
sheet 4
- Power/Power Indicators
- EEPROM
- CAD NOTE:
  Please place these capacitors
  next to the VCC and GND pins.
- MCU Circuitry
- MCU KL17
- SWD Connector
- Reset
- ROM Bootloader Activation
- MCU Decoupling Caps
- CAD NOTE:
  Place these capacitors
  near their respective CPU pin
  (VDDA to VSSA)
sheet 5
- Test Points/Connectors
- SPI Switch
- Interrupt Switch
sheet 6
- SPI/USB Converter - KL25
- KL25Z USB CONNECTOR
- 3V3 from USB
- Power Switch
- Power from Tower
- Power from On-Board USB
- 20mOhm Resistor
  in layout
- SWD CONNECTOR
- CAD NOTE:
  Please place these capacitors
  near their respective CPU pin
  (VREFH to VREFL
  and VDDA to VSSA).
  Decoupling capacitors
  shall be used for these
  pins: VDD1, VDD2, VDDA.
- KL25Z Bootloader Activation
- CAD NOTE:
  Please place P3V3_KL25Z
  capacitor close to the
  VOUT33 pin.
